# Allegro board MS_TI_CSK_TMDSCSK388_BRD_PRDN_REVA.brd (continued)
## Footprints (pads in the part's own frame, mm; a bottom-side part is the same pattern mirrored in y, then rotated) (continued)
XTAL4_FA-238V_130X105_SMD
  rect 1.397x1.194 smd: 1(-1.1,-0.8) 2(1.1,-0.8) 3(1.1,0.8) 4(-1.1,0.8)
XTAL_9HT10_130X60_SMD
  rect 0.991x1.803 smd: 1(-1.25,0) 2(1.25,0)

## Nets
DGND: C3.2 C4.2 C5.2 C6.2 C7.2 C8.2 C9.2 C12.2 C13.2 C14.2 C15.2 C16.2 C17.2 C18.2 C19.2 C20.2 C21.2 C22.2 C23.2 C24.2 C25.2 C26.2 C27.2 C28.2 C29.2 C30.2 C31.2 C32.2 C33.2 C34.2 C35.2 C36.2 C37.2 C38.2 C39.1 C40.2 C41.2 C42.2 C43.2 C44.2 C45.2 C46.1 C47.1 C48.1 C49.1 C50.1 C51.2 C52.2 C53.2 C54.2 C55.2 C56.2 C57.2 C58.2 C67.2 C68.2 C69.2 C70.2 C72.2 C73.2 C74.2 C76.2 C78.2 C79.2 C80.2 C81.2 C82.2 C83.2 C85.2 C86.1 C87.2 C88.2 C89.2 C90.2 C91.2 C92.2 C93.2 C94.2 C95.1 C96.1 C97.1 C99.1 C100.2 C101.2 C102.2 C103.2 C104.2 C105.2 C106.2 C107.2 C108.1 C109.1 C110.1 C111.1 C112.1 C113.2 C114.2 C115.2 C116.2 C117.2 C118.2 C119.2 C120.2 C121.1 C122.2 C123.2 C124.2 C125.2 C126.2 C127.2 C128.1 C129.2 C130.2 C131.2 C132.1 C133.1 C134.1 C135.2 C136.1 C137.2 C138.2 C139.1 C140.2 C141.2 C142.2 C143.2 C144.2 C145.2 C146.2 C147.2 C148.2 C149.1 C150.1 C151.2 C152.2 C153.2 C154.1 C155.2 C156.2 C157.2 C158.2 C159.2 C160.1 C161.1 C162.2 C163.2 C164.2 C165.2 C166.2 C167.1 C168.2 C169.1 C170.2 C171.2 C172.2 C173.2 C174.1 C175.1 C176.2 C177.2 C178.2 C179.1 C180.2 C181.2 C182.2 C183.2 C184.2 C185.2 C186.2 C187.2 C188.2 C189.2 D1.5(ANODE) J1.2(GND1) J1.3(GND2) J2.2(GND1) J2.3(GND2) J3.6 J3.11(GND1) J3.12(GND2) J3.18 J3.24 J3.33(GND3) J3.34(GND4) J3.55(GND5) J3.56(GND6) J3.67 J3.77(GND7) J3.78(GND8) J4.11(GND1) J4.12(GND2) J4.23 J4.28 J4.33(GND3) J4.34(GND4) J4.42 J4.45 J4.48 J4.55(GND5) J4.56(GND6) J4.62 J4.65 J4.77(GND7) J4.78(GND8) J5.5 J5.11(GND1) J5.12(GND2) J5.17 J5.33(GND3) J5.34(GND4) J5.35 J5.55(GND5) J5.56(GND6) J5.63 J5.64 J5.65 J5.66 L1.2 L2.2 L3.2 LD1.1(CATHODE) MOD1.1(GND#1) MOD1.7(GND#7) MOD1.9(GND#9) MOD1.15(GND#15) MOD1.16(GND#16) MOD1.17(GND#17) MOD1.19(GND#19) MOD1.20(GND#20) MOD1.23(GND#23) MOD1.24(GND#24) MOD1.28(GND#28) MOD1.29(GND#29) MOD1.30(GND#30) MOD1.31(GND#31) MOD1.33(GND#33) MOD1.34(GND#34) MOD1.35(GND#35) MOD1.37(GND#37) MOD1.39(GND#39) MOD1.44(GND#44) MOD1.45(GND#45) MOD1.48(GND#48) MOD1.49(GND#49) MOD1.54(GND#54) MOD1.55(GND#55) MOD1.59(GND#59) MOD1.61(GND#61) MOD1.63(GND#63) MOD1.64(RESERVED4) MOD1.G1(GND#G1) MOD1.G2(GND#G2) MOD1.G3(GND#G3) MOD1.G4(GND#G4) MOD1.G5(GND#G5) MOD1.G6(GND#G6) MOD1.G7(GND#G7) MOD1.G8(GND#G8) MOD1.G9(GND#G9) MOD1.G10(GND#G10) MOD1.G11(GND#G11) MOD1.G12(GND#G12) MOD1.G13(GND#G13) MOD1.G14(GND#G14) MOD1.G15(GND#G15) MOD1.G16(GND#G16) MOD1.G17(GND#G17) MOD1.G18(GND#G18) MOD1.G19(GND#G19) MOD1.G20(GND#G20) MOD1.G21(GND#G21) MOD1.G22(GND#G22) MOD1.G23(GND#G23) MOD1.G24(GND#G24) MOD1.G25(GND#G25) MOD1.G26(GND#G26) MOD1.G27(GND#G27) MOD1.G28(GND#G28) MOD1.G29(GND#G29) MOD1.G30(GND#G30) MOD1.G31(GND#G31) MOD1.G32(GND#G32) MOD1.G33(GND#G33) MOD1.G34(GND#G34) MOD1.G35(GND#G35) MOD1.G36(GND#G36) Q1.4(S1) Q1.7(S2) Q3.4(S1) Q3.7(S2) R1.1 R6.1 R11.2 R12.2 R16.2 R18.2 R28.2 R30.2 R31.2 R32.2 R33.2 R34.2 R46.2 R48.2 R49.2 R50.2 R51.2 R53.2 R56.2 R58.2 R61.2 R63.2 R64.1 R66.1 R76.1 R81.2 R83.2 R92.2 R97.1 R99.2 R101.2 R102.1 R112.1 R113.1 R119.1 R120.2 R122.2 R132.1 U1.A1(DGND_C) U1.A7(GND_CTRL_B) U1.A8(GND_CTRL_A) U1.B1(DGND_B) U1.B2(DGND_A) U1.C1(GND1_C) U1.C2(GND1_B) U1.D3(GND1_A) U1.D6(AGND_A) U1.E5(AGND_C) U1.E6(AGND_B) U1.F5(AGND_D) U1.G4(AGND_E) U1.H5(AGND_K) U1.H6(AGND_F) U1.J1(GND2_B) U1.J2(GND2_A) U1.J3(AGND_G) U1.J4(AGND_H) U1.J6(AGND_I) U1.J7(GNDIO_B) U1.J8(GNDIO_A) U1.K3(AGND_J) U1.M8(AGND2_B) U1.N8(AGND2_A) U2.8(GND1) U2.9(GND2) U2.14(2\O\E\) U2.15(1\O\E\) U2.17(PAD) U3.11(GND) U3.21(PAD) U4.8(GND) U4.9(3A) U4.12(4A) U4.15(O\E\) U4.17(EP) U5.8(GND1) U5.9(GND2) U5.14(2\O\E\) U5.15(1\O\E\) U5.17(PAD) U6.A9(VSS1) U6.B1(VSSQ1) U6.B3(VSS2) U6.B9(VSSQ2) U6.D1(VSSQ3) U6.D8(VSSQ4) U6.E1(VSS3) U6.E2(VSSQ5) U6.E8(VSSQ6) U6.F9(VSSQ7) U6.G1(VSSQ8) U6.G8(VSS4) U6.G9(VSSQ9) U6.J2(VSS5) U6.J8(VSS6) U6.M1(VSS7) U6.M9(VSS8) U6.P1(VSS9) U6.P9(VSS10) U6.T1(VSS11) U6.T9(VSS12) U7.A1(VSS#A1) U7.A31(VSS#A31) U7.AA13(VSS#AA13) U7.AA14(VSS#AA14) U7.AA15(VSS#AA15) U7.AA16(VSS#AA16) U7.AA17(VSS#AA17) U7.AA18(VSS#AA18) U7.AA27(VSS#AA27) U7.AC7(VSSA_CSI2#AC7) U7.AC25(VSS#AC25) U7.AD3(VSS#AD3) U7.AD4(VSS#AD4) U7.AD5(VSS#AD5) U7.AD6(VSS#AD6) U7.AD7(VSS#AD7) U7.AD24(VSS#AD24) U7.AD25(VSS#AD25) U7.AE5(VSS#AE5) U7.AE6(VSS#AE6) U7.AE7(VSS#AE7) U7.AE8(VSS#AE8) U7.AE9(VSS#AE9) U7.AE12(VSS#AE12) U7.AE19(VSS#AE19) U7.AE20(VSS#AE20) U7.AE23(VSS#AE23) U7.AE24(VSS#AE24) U7.AE25(VSS#AE25) U7.AE26(VSS#AE26) U7.AE27(VSS#AE27) U7.AE28(VSS#AE28) U7.AF7(VSS#AF7) U7.AF12(VSS#AF12) U7.AF20(VSS#AF20) U7.AF24(VSS#AF24) U7.AF25(VSS#AF25) U7.AG7(VSS#AG7) U7.AG11(VSS#AG11) U7.AG19(VSS#AG19) U7.AG24(VSS#AG24) U7.AG25(VSS#AG25) U7.AH7(VSS#AH7) U7.AH12(VSS#AH12) U7.AH20(VSS#AH20) U7.AL1(VSS#AL1) U7.AL31(VSS#AL31) U7.C8(VSSA_VDAC) U7.D8(VSS#D8) U7.D20(VSSA_USB#D20) U7.D25(VSS#D25) U7.E7(VSS#E7) U7.E8(VSS#E8) U7.E21(VSS#E21) U7.E25(VSS#E25) U7.F7(VSS#F7) U7.F8(VSS#F8) U7.F20(VSS#F20) U7.F25(VSS#F25) U7.G4(VSS#G4) U7.G5(VSS#G5) U7.G6(VSS#G6) U7.G7(VSS#G7) U7.G8(VSS#G8) U7.G9(VSSA_HDMI#G9) U7.G20(VSS#G20) U7.G23(VSS#G23) U7.G24(VSS#G24) U7.G25(VSS#G25) U7.G26(VSS#G26) U7.G27(VSS#G27) U7.H7(VSS#H7) U7.H8(VSSA_HDMI#H8) U7.H26(VSS#H26) U7.J7(VSS#J7) U7.L16(VSS#L16) U7.M16(VSS#M16) U7.N13(VSS#N13) U7.N14(VSS#N14) U7.N16(VSS#N16) U7.N17(VSS#N17) U7.N19(VSSA_USB#N19) U7.N20(VSSA_USB#N20) U7.P11(VSS#P11) U7.P12(VSS#P12) U7.P14(VSS#P14) U7.P18(VSS#P18) U7.R11(VSS#R11) U7.R12(VSS#R12) U7.R14(VSS#R14) U7.R18(VSS#R18) U7.R20(VSS#R20) U7.R21(VSS#R21) U7.T11(VSS#T11) U7.T12(VSS#T12) U7.T14(VSS#T14) U7.T15(VSS#T15) U7.T16(VSS#T16) U7.T19(VSS#T19) U7.T20(VSS#T20) U7.T21(VSS#T21) U7.U14(VSS#U14) U7.U18(VSS#U18) U7.U23(VSS#U23) U7.V14(VSSA_CSI2#V14) U7.V18(VSS#V18) U7.W16(VSS#W16) U7.W17(VSS#W17) U7.Y16(VSS#Y16) U7.Y17(VSS#Y17) U7.Y25(VSS#Y25) U7.Y26(VSS#Y26) U7.Y28(VSS#Y28) U8.A9(VSS1) U8.B1(VSSQ1) U8.B3(VSS2) U8.B9(VSSQ2) U8.D1(VSSQ3) U8.D8(VSSQ4) U8.E1(VSS3) U8.E2(VSSQ5) U8.E8(VSSQ6) U8.F9(VSSQ7) U8.G1(VSSQ8) U8.G8(VSS4) U8.G9(VSSQ9) U8.J2(VSS5) U8.J8(VSS6) U8.M1(VSS7) U8.M9(VSS8) U8.P1(VSS9) U8.P9(VSS10) U8.T1(VSS11) U8.T9(VSS12) U9.2(GND) U10.2(GND) U11.2(GND) U12.8(GND1) U12.9(GND2) U12.14(2\O\E\) U12.15(1\O\E\) U12.17(PAD) U13.13(VSS1) U13.25(VSS2) U13.36(VSS3) U13.48(VSS4) U14.4(VTTGND) U14.7(GND) U14.10(PGND) U14.21(EP)
VCC_3V3: C15.1 C20.1 C23.1 C35.1 C40.1 C45.1 C55.1 C56.1 C67.1 C69.1 C80.1 C81.1 C82.1 C83.1 C91.1 C100.1 C101.1 C102.1 C103.1 C114.1 C176.1 C177.1 C178.1 C181.1 C189.1 MOD1.46(VBAT_IN#46) MOD1.47(VBAT_IN#47) R7.1 R10.1 R20.1 R22.1 R23.1 R24.1 R25.1 R26.1 R29.1 R35.1 R40.1 R42.1 R43.1 R44.1 R45.1 R55.1 R57.1 R59.1 R60.1 R62.1 R67.1 R69.1 R70.1 R75.1 R84.1 R85.1 R91.1 R95.1 R96.1 R103.1 R118.2 R121.1 R130.1 R131.1 TP14.1(TP) U1.N7(VDDIO) U2.1(VCCA) U3.19(VCCB) U4.16(VCC) U5.1(VCCA) U7.D16(DVDD#D16) U7.E17(DVDD#E17) U7.F16(DVDD#F16) U7.L5(DVDD#L5) U7.M4(DVDD#M4) U7.M6(DVDD#M6) U7.M7(DVDD#M7) U7.N10(DVDD#N10) U7.N11(DVDD#N11) U7.R5(DVDD_GPMC#R5) U7.R7(DVDD_GPMC#R7) U7.T4(DVDD_GPMC#T4) U7.T6(DVDD_GPMC#T6) U7.T7(DVDD_GPMC#T7) U7.T25(DVDD_SD#T25) U7.T26(DVDD#T26) U7.T28(DVDD#T28) U7.U25(DVDD_SD#U25) U7.U27(DVDD#U27) U7.W5(DVDD_RGMII#W5) U7.W7(DVDD_RGMII#W7) U7.Y4(DVDD_RGMII#Y4) U7.Y6(DVDD_RGMII#Y6) U7.Y7(DVDD_RGMII#Y7) U9.1(IN) U9.3(EN) U10.4(VCC) U11.5(VCC) U12.1(VCCA) U13.12(VCC1) U13.34(VCC2) U13.37(VCC3) U13.39(VCC4)
VCC_5V0: C6.1 C7.1 C13.1 C14.1 C16.1 C17.1 C19.1 C22.1 C33.1 C38.1 C42.1 C78.1 J4.83 J4.85 J4.87 Q2.1(D1) Q2.2(D2) Q2.5(D3) Q2.6(D4) Q2.8(D5) Q4.1(D1) Q4.2(D2) Q4.5(D3) Q4.6(D4) Q4.8(D5) R88.1 R94.1 TP4.1(TP) U1.A5(V5IN) U1.B6(VCC7) U1.D8(VCC5) U1.E8(VCCS) U1.L1(VCC4) U1.N3(VCC3) U14.12(V5IN)
VCC_CAM: C118.1 J4.22 R117.1 R118.1 U7.D12(DVDD_C#D12) U7.E13(DVDD_C#E13) U7.F12(DVDD_C#F12) U7.G12(DVDD_C#G12) U7.G13(DVDD_C#G13)
VDD_DDR: C43.1 C51.1 C52.1 C53.1 C93.1 C98.1 C104.1 C105.1 C107.1 C121.2 C122.1 C127.1 C128.2 C135.1 C141.1 C143.1 C144.1 C145.1 C146.1 C147.1 C162.1 C163.1 C165.1 C166.1 C170.1 C173.1 C182.1 C183.1 C184.1 C185.1 C187.1 C188.1 L8.2 R72.1 U6.A1(VDDQ1) U6.A8(VDDQ2) U6.B2(VDD1) U6.C1(VDDQ3) U6.C9(VDDQ4) U6.D2(VDDQ5) U6.D9(VDD2) U6.E9(VDDQ6) U6.F1(VDDQ7) U6.G7(VDD3) U6.H2(VDDQ8) U6.H9(VDDQ9) U6.K2(VDD4) U6.K8(VDD5) U6.N1(VDD6) U6.N9(VDD7) U6.R1(VDD8) U6.R9(VDD9) U7.AB14(DVDD_DDR[0]#AB14) U7.AB15(DVDD_DDR[0]#AB15) U7.AB17(DVDD_DDR[0]#AB17) U7.AB18(DVDD_DDR[0]#AB18) U7.AC15(DVDD_DDR[0]#AC15) U7.AC17(DVDD_DDR[0]#AC17) U7.AC18(DVDD_DDR[0]#AC18) U7.AE15(DVDD_DDR[0]#AE15) U7.AE16(DVDD_DDR[0]#AE16) U7.AF16(DVDD_DDR[0]#AF16) U7.AG15(DVDD_DDR[0]#AG15) U7.AH16(DVDD_DDR[0]#AH16) U8.A1(VDDQ1) U8.A8(VDDQ2) U8.B2(VDD1) U8.C1(VDDQ3) U8.C9(VDDQ4) U8.D2(VDDQ5) U8.D9(VDD2) U8.E9(VDDQ6) U8.F1(VDDQ7) U8.G7(VDD3) U8.H2(VDDQ8) U8.H9(VDDQ9) U8.K2(VDD4) U8.K8(VDD5) U8.N1(VDD6) U8.N9(VDD7) U8.R1(VDD8) U8.R9(VDD9) U14.2(VLDOIN) U14.9(VDDQSNS)
VDD_DDR_VREF: C90.1 C106.1 C132.2 C142.1 C164.1 C186.1 U6.H1(VREFDQ) U6.M8(VREFCA) U7.AL18(VREFSSTL_DDR[0]) U8.H1(VREFDQ) U8.M8(VREFCA) U14.5(VTTREF)
VDDR_VTT: C47.2 C48.2 C49.2 C50.2 C92.1 C94.1 C95.2 C96.2 C97.2 C108.2 C109.2 C112.2 C154.2 C169.2 RA4.1 RA4.2 RA4.3 RA4.4 RA6.1 RA6.2 RA6.3 RA6.4 RA7.1 RA7.2 RA7.3 RA7.4 RA8.1 RA8.2 RA8.3 RA8.4 RA10.1 RA10.2 RA10.3 RA10.4 RA11.1 RA11.2 RA11.3 RA11.4 U14.1(VTTSNS) U14.3(VTT)
BB_PMIC_3V3: J4.76 J4.80 J4.82 J4.84 J4.86 J4.88 R27.2
BB_VCC3V3: J4.16 J4.18 J4.20 R75.2
CC_RST: J3.54 R84.2 U11.3(B)
CLK32OUT_PMIC: R19.2 R36.1
CLKIN32: R82.2 U7.AJ31(CLKIN32/CLKOUT0/TIM3_IO/GP3[31])
CORE_CVDD: C87.1 C88.1 C89.1 C124.1 C125.1 C126.1 C129.1 C131.1 C137.1 C138.1 C140.1 C153.1 R15.2 R141.2 U7.P15(CVDD#P15) U7.P17(CVDD#P17) U7.R15(CVDD#R15) U7.R17(CVDD#R17) U7.T13(CVDD#T13) U7.T17(CVDD#T17) U7.T18(CVDD#T18) U7.U11(CVDD#U11) U7.U12(CVDD#U12) U7.U15(CVDD#U15) U7.U17(CVDD#U17) U7.V11(CVDD#V11) U7.V12(CVDD#V12) U7.V15(CVDD#V15) U7.V17(CVDD#V17) U7.W13(CVDD#W13) U7.W14(CVDD#W14) U7.W19(CVDD#W19) U7.W20(CVDD#W20) U7.Y13(CVDD#Y13) U7.Y14(CVDD#Y14) U7.Y19(CVDD#Y19) U7.Y20(CVDD#Y20)
CVDD_ARM: C113.1 C120.1 C150.2 C151.1 R17.2 U7.K17(CVDD_ARM#K17) U7.L17(CVDD_ARM#L17) U7.L18(CVDD_ARM#L18) U7.M13(CVDD_ARM#M13) U7.M14(CVDD_ARM#M14) U7.M17(CVDD_ARM#M17)
CVDD_HDVICP: C39.2 C41.1 C158.1 C168.1 R21.2 U7.U20(CVDD_HDVICP#U20) U7.U21(CVDD_HDVICP#U21) U7.V20(CVDD_HDVICP#V20) U7.V21(CVDD_HDVICP#V21) U7.W22(CVDD_HDVICP#W22)
DDR_PGOOD: R103.2 U11.6(C) U14.20(PGOOD)
DM388_BT_EN: U7.M1(GPMC_A[16]/GP2[5]) U12.4(1A1)
DM388_BTMODE[0]: R55.2 R56.1 U7.W6(GPMC_D[0]/BTMODE[0]) U13.29(I/O0)
DM388_BTMODE[1]: R40.2 R46.1 U7.W4(GPMC_D[1]/BTMODE[1]) U13.30(I/O1)
DM388_BTMODE[2]: R28.1 SW1.2 U7.W3(GPMC_D[2]/BTMODE[2]) U13.31(I/O2)
DM388_BTMODE[3]: R43.2 R49.1 U7.U2(GPMC_D[3]/BTMODE[3]) U13.32(I/O3)
DM388_BTMODE[4]: R25.2 R33.1 U7.W9(GPMC_D[4]/BTMODE[4]) U13.41(I/O4)
DM388_BTMODE[5]: R16.1 U7.T5(GPMC_D[5]/BTMODE[5]) U13.42(I/O5)
DM388_BTMODE[6]: R18.1 U7.T3(GPMC_D[6]/BTMODE[6]) U13.43(I/O6)
DM388_BTMODE[7]: R23.2 R31.1 U7.T2(GPMC_D[7]/BTMODE[7]) U13.44(I/O7)
DM388_BTMODE[8]: R44.2 R50.1 U7.T1(GPMC_D[8]/BTMODE[8]) U13.26(I/O8)
DM388_BTMODE[9]: R42.2 R48.1 U7.T8(GPMC_D[9]/BTMODE[9]) U13.27(I/O9)
DM388_BTMODE[10]: R24.2 R32.1 U7.R6(GPMC_D[10]/BTMODE[10]) U13.28(I/O10)
DM388_BTMODE[11]: R60.2 R101.1 U7.R4(GPMC_D[11]/BTMODE[11]) U13.33(I/O11)
DM388_BTMODE[12]: R29.2 U7.R3(GPMC_D[12]/BTMODE[12]) U13.40(I/O12)
DM388_BTMODE[13]: R45.2 R51.1 U7.R2(GPMC_D[13]/BTMODE[13]) U13.45(I/O13)
DM388_BTMODE[14]: R26.2 R34.1 U7.R1(GPMC_D[14]/BTMODE[14]) U13.46(I/O14)
DM388_BTMODE[15]: R22.2 R30.1 U7.P2(GPMC_D[15]/BTMODE[15]) U13.47(I/O15)
DM388_CAM_DAT0: J3.1 U7.C2(VOUT[1]_R_CR[0]/CAM_D[0]/GPMC_A)
DM388_CAM_DAT1: J3.3 U7.C1(VOUT[1]_R_CR[1]/CAM_D[1]/GPMC_A)
DM388_CAM_DAT2: J3.5 U7.B2(VOUT[1]_G_Y_YC[0]/CAM_D[2]/GPMC)
DM388_CAM_DAT3: J3.7 U7.A2(VOUT[1]_G_Y_YC[1]/CAM_D[3]/GPMC)
DM388_CAM_DAT4: J3.9 U7.A3(VIN[0]B_FLD/CAM_D[4]/GP0[21])
DM388_CAM_DAT5: J3.13 U7.B4(VIN[0]A_FLD/CAM_D[5]/GP0[20])
DM388_CAM_DAT6: J3.15 U7.C5(VIN[0]B_DE/CAM_D[6]/GP0[19])
DM388_CAM_DAT7: J3.17 U7.B5(VIN[0]A_DE/CAM_D[7]/GP0[18])
DM388_CAM_DAT8: J3.19 U7.K11(VIN[0]A_D[16]/CAM_D[8]/I2C[2]_S)
DM388_CAM_DAT9: J3.21 U7.E12(VIN[0]A_D[17]/CAM_D[9]/EMAC[1]_)
DM388_CAM_DAT10: J3.23 U7.K10(VIN[0]A_D[18]/CAM_D[10]/EMAC[1])
DM388_CAM_DAT11: J3.25 U7.D7(VIN[0]A_D[19]/CAM_D[11]/EMAC[1])
DM388_CAM_DAT12: J3.27 U7.F9(VIN[0]A_D[20]/CAM_D[12]/EMAC[1])
DM388_CAM_DAT13: J3.29 U7.C7(VIN[0]A_D[21]/CAM_D[13]/EMAC[1])
DM388_CAM_DAT14: J3.31 U7.A6(VIN[0]A_D[22]/CAM_D[14]/EMAC[1])
DM388_CAM_DAT15: J3.35 U7.A5(VIN[0]A_D[23]/CAM_D[15]/EMAC[1])
DM388_CAM_FLD: J3.41 U4.2(1B1)
DM388_CAM_FLD_UT_CTSN: U4.4(1A) U7.J10(VOUT[1]_FLD/CAM_FLD/CAM_WEN/GPM)
DM388_CAM_HS: J3.37 U7.D5(VOUT[1]_B_CB_C[1]/CAM_HS/GPMC_A)
DM388_CAM_PCLK: J3.43 R142.2 U4.5(2B1)
DM388_CAM_PCLK_UT_RTSN: R142.1 U4.7(2A) U7.B3(VOUT[0]_FLD/CAM_PCLK/GPMC_A[12])
DM388_CAM_RESET: J3.47 U7.H16(VIN[0]A_D[13]_BD[5]/CAM_RESET/G)
DM388_CAM_SHUTTER: J3.51 U7.H13(VIN[0]A_D[15]_BD[7]/CAM_SHUTTER)
DM388_CAM_STROBE: J3.49 U7.F13(VIN[0]A_D[14]_BD[6]/CAM_STROBE/)
DM388_CAM_VS: J3.39 U7.H9(VOUT[1]_B_CB_C[0]/CAM_VS/GPMC_A)
DM388_CAM_WEN: J3.45 U7.H17(VIN[0]A_D[11]_BD[3]/CAM_WEN/GP2)
DM388_CSI_DX0: J4.38 U7.AB2(CSI2_DX[0])
DM388_CSI_DX1: J4.44 U7.AA1(CSI2_DX[1])
DM388_CSI_DX2: J4.50 U7.AA2(CSI2_DX[2])
DM388_CSI_DX3: J4.58 U7.W2(CSI2_DX[3])
DM388_CSI_DX4: J4.64 U7.V1(CSI2_DX[4])
DM388_CSI_DY0: J4.40 U7.AC2(CSI2_DY[0])
DM388_CSI_DY1: J4.46 U7.AB1(CSI2_DY[1])
DM388_CSI_DY2: J4.52 U7.Y2(CSI2_DY[2])
DM388_CSI_DY3: J4.60 U7.W1(CSI2_DY[3])
DM388_CSI_DY4: J4.66 U7.V2(CSI2_DY[4])
DM388_DDR0_A0: RA7.8 U6.N3(A0) U7.AL24(DDR[0]_A[0]) U8.N3(A0)
DM388_DDR0_A1: RA4.7 U6.P7(A1) U7.AC22(DDR[0]_A[1]) U8.P7(A1)
DM388_DDR0_A2: RA7.7 U6.P3(A2) U7.AJ23(DDR[0]_A[2]) U8.P3(A2)
DM388_DDR0_A3: RA8.6 U6.N2(A3) U7.AJ27(DDR[0]_A[3]) U8.N2(A3)
DM388_DDR0_A4: RA11.5 U6.P8(A4) U7.AK28(DDR[0]_A[4]) U8.P8(A4)
DM388_DDR0_A5: RA8.7 U6.P2(A5) U7.AH27(DDR[0]_A[5]) U8.P2(A5)
DM388_DDR0_A6: RA11.8 U6.R8(A6) U7.AK30(DDR[0]_A[6]) U8.R8(A6)
DM388_DDR0_A7: RA8.8 U6.R2(A7) U7.AG23(DDR[0]_A[7]) U8.R2(A7)
DM388_DDR0_A8: RA4.5 U6.T8(A8) U7.AL29(DDR[0]_A[8]) U8.T8(A8)
DM388_DDR0_A9: RA7.6 U6.R3(A9) U7.AK29(DDR[0]_A[9]) U8.R3(A9)
DM388_DDR0_A10: RA10.8 U6.L7(A10/AP) U7.AD23(DDR[0]_A[10]) U8.L7(A10/AP)
DM388_DDR0_A11: RA4.6 U6.R7(A11) U7.AK24(DDR[0]_A[11]) U8.R7(A11)
DM388_DDR0_A12: RA4.8 U6.N7(A12/B\C\) U7.AH23(DDR[0]_A[12]) U8.N7(A12/B\C\)
DM388_DDR0_A13: RA7.5 U6.T3(A13) U7.AK23(DDR[0]_A[13]) U8.T3(A13)
DM388_DDR0_A14: RA11.6 U6.T7(A14) U7.AL23(DDR[0]_A[14]) U8.T7(A14)
DM388_DDR0_BA0: RA8.5 U6.M2(BA0) U7.AK26(DDR[0]_BA[0]) U8.M2(BA0)
DM388_DDR0_BA1: RA11.7 U6.N8(BA1) U7.AF23(DDR[0]_BA[1]) U8.N8(BA1)
DM388_DDR0_BA2: RA10.5 U6.M3(BA2) U7.AH25(DDR[0]_BA[2]) U8.M3(BA2)
DM388_DDR0_CASN: RA6.7 U6.K3(C\A\S\) U7.AK25(DDR[0]_CASN) U8.K3(C\A\S\)
DM388_DDR0_CKE: RA10.7 U6.K9(CKE) U7.AD20(DDR[0]_CKE) U8.K9(CKE)
DM388_DDR0_CLK: R107.1 U6.J7(CK) U7.AL27(DDR[0]_CLK) U8.J7(CK)
DM388_DDR0_CLKN: R108.1 U6.K7(C\K\) U7.AK27(DDR[0]_CLKN) U8.K7(C\K\)
DM388_DDR0_CS0N: RA6.8 U6.L2(C\S\) U7.AB21(DDR[0]_CS[0]N) U8.L2(C\S\)
DM388_DDR0_DQ0: U6.E3(DQ0) U7.AL9(DDR[0]_D[0])
DM388_DDR0_DQ1: U6.F7(DQ1) U7.AK9(DDR[0]_D[1])
DM388_DDR0_DQ2: U6.F2(DQ2) U7.AK10(DDR[0]_D[2])
DM388_DDR0_DQ3: U6.F8(DQ3) U7.AJ11(DDR[0]_D[3])
DM388_DDR0_DQ4: U6.H3(DQ4) U7.AH11(DDR[0]_D[4])
DM388_DDR0_DQ5: U6.H8(DQ5) U7.AD9(DDR[0]_D[5])
DM388_DDR0_DQ6: U6.G2(DQ6) U7.AF11(DDR[0]_D[6])
DM388_DDR0_DQ7: U6.H7(DQ7) U7.AL12(DDR[0]_D[7])
DM388_DDR0_DQ8: U6.D7(DQ8) U7.AJ12(DDR[0]_D[8])
DM388_DDR0_DQ9: U6.C3(DQ9) U7.AG12(DDR[0]_D[9])
DM388_DDR0_DQ10: U6.C8(DQ10) U7.AD12(DDR[0]_D[10])
DM388_DDR0_DQ11: U6.C2(DQ11) U7.AB12(DDR[0]_D[11])
DM388_DDR0_DQ12: U6.A7(DQ12) U7.AK13(DDR[0]_D[12])
DM388_DDR0_DQ13: U6.A2(DQ13) U7.AC13(DDR[0]_D[13])
DM388_DDR0_DQ14: U6.B8(DQ14) U7.AL14(DDR[0]_D[14])
DM388_DDR0_DQ15: U6.A3(DQ15) U7.AK14(DDR[0]_D[15])
DM388_DDR0_DQ16: U7.AH15(DDR[0]_D[16]) U8.E3(DQ0)
DM388_DDR0_DQ17: U7.AF15(DDR[0]_D[17]) U8.F7(DQ1)
DM388_DDR0_DQ18: U7.AD15(DDR[0]_D[18]) U8.F2(DQ2)
DM388_DDR0_DQ19: U7.AK16(DDR[0]_D[19]) U8.F8(DQ3)
DM388_DDR0_DQ20: U7.AJ16(DDR[0]_D[20]) U8.H3(DQ4)
DM388_DDR0_DQ21: U7.AG16(DDR[0]_D[21]) U8.H8(DQ5)
DM388_DDR0_DQ22: U7.AD16(DDR[0]_D[22]) U8.G2(DQ6)
DM388_DDR0_DQ23: U7.AC16(DDR[0]_D[23]) U8.H7(DQ7)
DM388_DDR0_DQ24: U7.AK19(DDR[0]_D[24]) U8.D7(DQ8)
DM388_DDR0_DQ25: U7.AJ19(DDR[0]_D[25]) U8.C3(DQ9)
DM388_DDR0_DQ26: U7.AH19(DDR[0]_D[26]) U8.C8(DQ10)
DM388_DDR0_DQ27: U7.AF19(DDR[0]_D[27]) U8.C2(DQ11)
DM388_DDR0_DQ28: U7.AD19(DDR[0]_D[28]) U8.A7(DQ12)
DM388_DDR0_DQ29: U7.AC19(DDR[0]_D[29]) U8.A2(DQ13)
DM388_DDR0_DQ30: U7.AJ20(DDR[0]_D[30]) U8.B8(DQ14)
DM388_DDR0_DQ31: U7.AG20(DDR[0]_D[31]) U8.A3(DQ15)
DM388_DDR0_DQM0: U6.E7(LDM) U7.AL8(DDR[0]_DQM[0])
DM388_DDR0_DQM1: U6.D3(UDM) U7.AK12(DDR[0]_DQM[1])
DM388_DDR0_DQM2: U7.AJ15(DDR[0]_DQM[2]) U8.E7(LDM)
DM388_DDR0_DQM3: U7.AK18(DDR[0]_DQM[3]) U8.D3(UDM)
DM388_DDR0_DQS0: U6.F3(LDQS) U7.AL11(DDR[0]_DQS[0])
DM388_DDR0_DQS0N: U6.G3(L\D\Q\S\) U7.AK11(DDR[0]_DQS[0]N)
DM388_DDR0_DQS1: U6.C7(UDQS) U7.AL15(DDR[0]_DQS[1])
DM388_DDR0_DQS1N: U6.B7(U\D\Q\S\) U7.AK15(DDR[0]_DQS[1]N)
DM388_DDR0_DQS2: U7.AL17(DDR[0]_DQS[2]) U8.F3(LDQS)
DM388_DDR0_DQS2N: U7.AK17(DDR[0]_DQS[2]N) U8.G3(L\D\Q\S\)
DM388_DDR0_DQS3: U7.AL20(DDR[0]_DQS[3]) U8.C7(UDQS)
DM388_DDR0_DQS3N: U7.AK20(DDR[0]_DQS[3]N) U8.B7(U\D\Q\S\)
DM388_DDR0_ODT0: RA6.5 U6.K1(ODT) U7.AL21(DDR[0]_ODT[0]) U8.K1(ODT)
DM388_DDR0_RASN: RA6.6 U6.J3(R\A\S\) U7.AJ25(DDR[0]_RASN) U8.J3(R\A\S\)
DM388_DDR0_RST: R72.2 U6.T2(R\E\S\E\T\) U7.AA20(DDR[0]_RST) U8.T2(R\E\S\E\T\)
DM388_DDR0_VTP: R122.1 U7.AL30(DDR[0]_VTP)
DM388_DDR0_WEN: RA10.6 U6.L3(W\E\) U7.AL26(DDR[0]_WEN) U8.L3(W\E\)
DM388_EMU0: J3.30 R78.2
DM388_EMU1: J3.32 R77.2
DM388_GMII_COL: J4.54 U7.AH1(EMAC[0]_MCOL/EMAC[0]_RGRXCTL/VI)
DM388_GMII_CRS: J4.14 U7.AH2(EMAC[0]_MCRS/EMAC[0]_RGRXD[2]/V)
DM388_GMII_GMTCLK: J4.25 R73.1
DM388_GMII_MTCLK: J4.19 U7.AG4(EMAC[0]_MTCLK/EMAC[0]_RGRXC/VIN)
DM388_GMII_RCLK: J4.39 R106.2
DM388_GMII_RXD[0]: J4.47 R109.2
DM388_GMII_RXD[1]: J4.49 U7.AL2(EMAC[0]_MRXD[1]/EMAC[0]_RGRXD[0)
DM388_GMII_RXD[2]: J4.51 U7.AL3(EMAC[0]_MRXD[2]/EMAC[0]_RGRXD[1)
DM388_GMII_RXD[3]: J4.53 U7.AK3(EMAC[0]_MRXD[3]/EMAC[1]_RGRXCTL)
DM388_GMII_RXD[4]: J4.57 U7.AK4(EMAC[0]_MRXD[4]/EMAC[0]_RGRXD[3)
DM388_GMII_RXD[5]: J4.59 R104.2
DM388_GMII_RXD[6]: J4.61 R111.2
DM388_GMII_RXD[7]: J4.63 R110.2
DM388_GMII_RXDV: J4.41 U7.AJ6(EMAC[0]_MRXDV/EMAC[1]_RGRXD[1]/)
DM388_GMII_RXER: J4.43 U7.AJ2(EMAC[0]_MRXER/EMAC[0]_RGTXCTL/V)
DM388_GMII_TXD[0]: J4.17 RA2.5
DM388_GMII_TXD[1]: J4.15 RA2.6
DM388_GMII_TXD[2]: J4.13 RA2.7
DM388_GMII_TXD[3]: J4.9 RA2.8
DM388_GMII_TXD[4]: J4.7 RA3.5
DM388_GMII_TXD[5]: J4.5 RA3.6
DM388_GMII_TXD[6]: J4.3 RA3.7
DM388_GMII_TXD[7]: J4.1 RA3.8
DM388_GMII_TXEN: J4.27 R114.1
DM388_GP0[9]: J3.52 U7.AG30(AUD_CLKIN2/ATL_CLKOUT3/EDMA_EVT)
DM388_GP1[10]: J4.75 U7.AG1(EMAC_RMREFCLK/TIM2_IO/GP1[10])
DM388_GP1[14]: J4.74 U7.M5(GPMC_A[19]/TIM3_IO/GP1[14])
DM388_GP1[24]: J4.69 U7.AA12(GPMC_CS[1]N/GPMC_A[25]/GP1[24])
DM388_GP1[25]: J4.71 U7.AC3(GPMC_CS[2]N/GPMC_A[24]/GP1[25])
DM388_GP1[30]: J4.67 U7.Y11(GPMC_BE[1]N/GPMC_A[24]/EDMA_EVT)
DM388_GP3[3]: J4.73 U7.G2(VOUT[1]_B_CB_C[6]/EMAC[1]_MRXD[)
DM388_GP3[4]: J4.21 U7.H3(VOUT[1]_B_CB_C[7]/EMAC[1]_MRXD[)
DM388_GPMC_ALE: U7.AA10(GPMC_ADVN_ALE/GPMC_CS[6]N/TIM5_) U13.17(ALE)
DM388_GPMC_CLE: U7.Y3(GPMC_BE[0]N_CLE/GPMC_A[25]/EDMA) U13.16(CLE)
DM388_GPMC_CS[0]N: U7.AC9(GPMC_CS[0]N/GP1[23]) U13.9(C\E\)
DM388_GPMC_OEN_REN: U7.Y8(GPMC_OEN_REN) U13.8(R\E\)
DM388_GPMC_WAIT0: R20.2 U7.W8(GPMC_WAIT[0]/GPMC_A[26]/EDMA_EV) U13.7(R/B\)
DM388_GPMC_WEN: U7.Y5(GPMC_WEN) U13.18(W\E\)
DM388_GPMC_WPN: R35.2 U7.AF2(GPMC_CS[3]N/VIN[1]B_CLK/SPI[2]_) U13.19(W\P\)
DM388_HDMI_CEC: J4.6 U7.N2(GPMC_A[22]/SPI[2]_D[1]/HDMI_CEC)
DM388_HDMI_CLKN: J3.2 U7.B15(HDMI_CLKN)
DM388_HDMI_CLKP: J3.4 U7.A15(HDMI_CLKP)
DM388_HDMI_DN0: J3.8 U7.A14(HDMI_DN0)
DM388_HDMI_DN1: J3.14 U7.B13(HDMI_DN1)
DM388_HDMI_DN2: J3.20 U7.A12(HDMI_DN2)
DM388_HDMI_DP0: J3.10 U7.B14(HDMI_DP0)
DM388_HDMI_DP1: J3.16 U7.B12(HDMI_DP1)
DM388_HDMI_DP2: J3.22 U7.A11(HDMI_DP2)
DM388_HDMI_HPDET: J4.8 U7.R8(GPMC_A[23]/SPI[2]_SCLK/HDMI_HPD)
DM388_HDMI_SCL: J4.29 R67.2 U7.D2(I2C[1]_SCL/HDMI_SCL)
DM388_HDMI_SDA: J4.31 R70.2 U7.D1(I2C[1]_SDA/HDMI_SDA)
DM388_I2C0_SCL: R95.2 U1.M4(SCL) U7.T27(I2C[0]_SCL)
DM388_I2C0_SDA: R96.2 U1.M5(SDA) U7.T24(I2C[0]_SDA)
DM388_I2C2_SCL: J4.2 R130.2 U7.E31(UART0_DCDN/SPI[0]_SCS[3]N/I2C[2)
DM388_I2C2_SDA: J4.4 R121.2 U7.E29(UART0_DSRN/SPI[0]_SCS[2]N/I2C[2)
DM388_MCA[1]_AHCLKX: J3.79 R139.2
DM388_MCASP0_ACLKR: J5.23 R137.2
DM388_MCASP0_ACLKX: R52.1 R127.2
DM388_MCASP0_AFSR: J5.25 U7.AF30(MCA[0]_AFSR)
DM388_MCASP0_AFSX: R41.1 U7.AE29(MCA[0]_AFSX)
DM388_MCASP0_AXR0: R38.1 U7.AF29(MCA[0]_AXR[0])
DM388_MCASP0_AXR1: R90.1 U7.AE31(MCA[0]_AXR[1]/I2C[3]_SCL)
DM388_MCASP0_AXR2: J4.30 U7.AE30(MCA[0]_AXR[2]/I2C[3]_SDA)
DM388_MCASP0_AXR3: J4.32 U7.AC31(MCA[0]_AXR[3])
DM388_MCASP0_AXR4: J4.36 U7.AD26(MCA[0]_AXR[4])
DM388_MCASP0_AXR5: J4.79 U7.AD27(MCA[0]_AXR[5])
DM388_MCASP1_ACLKR: J5.21 R138.1
DM388_MCASP1_ACLKX: J3.81 R128.1
DM388_MCASP1_AFSR: J5.27 U7.AC24(MCA[1]_AFSR)
DM388_MCASP1_AFSX: J3.83 U7.AB22(MCA[1]_AFSX)
DM388_MCASP1_AXR0: J3.85 U7.Y22(MCA[1]_AXR[0]/SD0_DAT[4])
DM388_MCASP1_AXR1: J3.87 U7.Y21(MCA[1]_AXR[1]/SD0_DAT[5])
DM388_MDIO_CLK: J4.35 R65.1
DM388_MDIO_DAT: J4.37 U7.AG3(MDIO/GP1[12])
DM388_MMC0_CLK: R136.2 U3.20(B1)
DM388_MMC0_CMD: R126.2 U3.18(B2)
DM388_MMC0_DAT0: RA12.4 U3.17(B3)
DM388_MMC0_DAT1: RA12.3 U3.16(B4)
DM388_MMC0_DAT2: RA12.2 U3.15(B5)
DM388_MMC0_DAT3: RA12.1 U3.14(B6)
DM388_MMC1_CLK: J3.80 R135.1
DM388_MMC1_CMD: J3.82 R125.1
DM388_MMC1_DAT0: J3.84 RA13.5
DM388_MMC1_DAT1: J3.86 RA13.6
DM388_MMC1_DAT2: J3.88 RA13.7
DM388_MMC1_DAT3: J3.76 RA13.8
DM388_MMC1_DAT6/GP0_12: J4.70 U7.AB31(SD0_DAT[6]/GP0[12])
DM388_MMC1_DAT7/GP0_13: J4.72 U7.AC30(SD0_DAT[7]/GP0[13])
DM388_MMC1_SDCD: J3.75 U7.G28(SPI[0]_SCS[1]N/SD1_SDCD/EDMA_EV)
DM388_MMC2_CMD: J5.8 R105.2
DM388_MMC2_DAT0: J5.24 RA9.4
DM388_MMC2_DAT1: J5.22 RA9.3
DM388_MMC2_DAT2: J5.10 R115.2
DM388_MMC2_DAT3: J5.4 RA1.2
DM388_MMC2_DAT4: J5.6 RA1.1
DM388_MMC2_DAT5: J5.14 RA1.3
DM388_MMC2_DAT6: J5.16 RA1.4
DM388_MMC2_DAT7: J5.18 RA9.1
DM388_MMC2_DAT_0: RA9.5 U7.AC4(SD2_DAT[0]/GPMC_A[4]/GP1[14])
DM388_MMC2_DAT_1: RA9.6 U7.AC5(SD2_DAT[1]_SDIRQN/GPMC_A[3]/GP1)
DM388_MMC2_DAT_3: RA1.7 U7.AD1(SD2_DAT[3]/GPMC_A[1]/GP2[5])
DM388_MMC2_DAT_4: RA1.8 U7.AD2(SD2_DAT[4]/GPMC_A[27]/GPMC_A[23)
DM388_MMC2_DAT_5: RA1.6 U7.AE1(SD2_DAT[5]/GPMC_A[26]/GPMC_A[22)
DM388_MMC2_DAT_6: RA1.5 U7.AE2(SD2_DAT[6]/GPMC_A[25]/GPMC_A[21)
DM388_MMC2_DAT_7: RA9.8 U7.AE3(SD2_DAT[7]/GPMC_A[24]/GPMC_A[20)
DM388_MMC2_S_CLK: RA9.7 U7.AC6(SD2_SCLK/GP1[15])
DM388_MMC2_SCLK: J5.20 RA9.2
DM388_MUX_SEL: R53.1 U4.1(S) U7.N1(GPMC_A[21]/SPI[2]_D[0]/GP1[16])
DM388_PCIE_RXN0: J5.3 U7.J30(PCIE_RXN0)
DM388_PCIE_RXP0: J5.1 U7.K30(PCIE_RXP0)
DM388_PCIE_TXN0: C64.2 J5.9
DM388_PCIE_TXP0: C63.2 J5.7
DM388_PMIC_PWRON: J4.10 R94.2 U1.E4(PWRON)
DM388_PORN: R83.1 U7.AH30(PORN) U11.4(Y)
DM388_RSTOUT: J3.50 R81.1 U7.AJ30(RSTOUTN_WD_OUTN)
DM388_RTCK: J3.40 R124.2
DM388_SERDES_CLKN: C66.2 J5.15
DM388_SERDES_CLKP: C65.2 J5.13
DM388_SPI0_SCS[0]N: J3.70 U7.G29(SPI[0]_SCS[0]N)
DM388_SPI1_D[0]: J5.62 U7.N23(SPI[1]_D[0]/GP1[26])
DM388_SPI1_D[1]: J5.29 U7.M27(SPI[1]_D[1]/GP1[18])
DM388_SPI1_SCLK: J5.31 R123.2
DM388_SPI1_SCS[0]N: J5.61 U7.J29(SPI[1]_SCS[0]N/GP1[16])
DM388_SPI[0]_D[0]: J3.72 U7.J28(SPI[0]_D[0])
DM388_SPI[0]_D[1]: J3.74 U7.J27(SPI[0]_D[1])
DM388_SPI[0]_SCLK: J3.68 R129.2
DM388_TCLK: J3.38 U7.T29(TCLK)
DM388_TDI: J3.44 U7.N28(TDI)
DM388_TDO: J3.46 R133.2
DM388_TMS: J3.36 U7.T31(TMS)
DM388_TPS_SLEEP: U1.F1(SLEEP) U7.N9(GPMC_A[20]/SPI[2]_SCS[1]N/GP1[1)
DM388_TRSTN: J3.42 R120.1 U7.U24(TRSTN)
DM388_UART0_CTSN: J5.39 U7.D30(UART0_CTSN/SPI[1]_SCS[3]N/SD0_S)
DM388_UART0_RTSN: J5.37 U7.D31(UART0_RTSN/SPI[1]_SCS[2]N/SD2_S)
DM388_UART0_RXD: J3.71 U7.J26(UART0_RXD)
DM388_UART0_TXD: J3.69 R80.1
DM388_UART1_RXD: J3.28 U7.N26(UART0_RIN/UART1_RXD/GP1[5])
DM388_UART1_TXD: J3.26 R134.1
DM388_UART2_CTSN: U2.7(2A2) U4.3(1B2)
DM388_UART2_RTSN: U2.5(1A2) U4.6(2B2)
DM388_UART2_RXD: U2.6(2A1) U7.L22(UART2_RXD/I2C[3]_SCL/GP1[1])
DM388_UART2_TXD: R79.1 U2.4(1A1)
DM388_USB0_CE: J5.58 U7.B20(USB0_CE)
DM388_USB0_DM: J3.62 U7.B21(USB0_DM)
DM388_USB0_DP: J3.64 U7.A21(USB0_DP)
DM388_USB0_DRVVBUS: J3.66 U7.K23(USB0_DRVVBUS/GP0[7])
DM388_USB0_ID: J3.60 U7.A20(USB0_ID)
DM388_USB0_VBUSIN: J3.58 U7.B22(USB0_VBUSIN)
DM388_USB1_CE: J5.60 U7.C21(USB1_CE)
DM388_USB1_DM: J3.61 U7.B23(USB1_DM)
DM388_USB1_DP: J3.59 U7.A23(USB1_DP)
DM388_USB1_DRVVBUS: J3.63 U7.AF31(AUD_CLKIN0/MCA[0]_AHCLKX/ATL_CL)
DM388_USB1_ID: J3.65 U7.A24(USB1_ID)
DM388_USB1_VBUSIN: J3.57 U7.B24(USB1_VBUSIN)
DM388_VIN[0]A_CLK: J5.40 U7.C9(VIN[0]A_CLK/GP2[2])
DM388_VIN[0]A_D[0]: J5.46 U7.B18(VIN[0]A_D[0]/GP1[11])
DM388_VIN[0]A_D[1]: J5.49 U7.A17(VIN[0]A_D[1]/GP1[12])
DM388_VIN[0]A_D[2]: J5.50 U7.B17(VIN[0]A_D[2]/GP2[7])
DM388_VIN[0]A_D[3]: J5.52 U7.C17(VIN[0]A_D[3]/GP2[8])
DM388_VIN[0]A_D[4]: J5.54 U7.D17(VIN[0]A_D[4]/GP2[9])
DM388_VIN[0]A_D[5]: J5.53 U7.F17(VIN[0]A_D[5]/GP2[10])
DM388_VIN[0]A_D[6]: J5.59 U7.L20(VIN[0]A_D[6]/GP2[11])
DM388_VIN[0]A_D[7]: J5.57 U7.H20(VIN[0]A_D[7]/GP2[12])
DM388_VIN[0]A_D[8]_BD[0]: J5.47 U7.B16(VIN[0]A_D[8]_BD[0]/GP2[13])
DM388_VIN[0]A_D[9]_BD[1]: J5.48 U7.C16(VIN[0]A_D[9]_BD[1]/GP2[14])
DM388_VIN[0]A_D[10]_BD[2]: J5.45 U7.E16(VIN[0]A_D[10]_BD[2]/GP2[15])
DM388_VIN[0]A_D[12]_BD[4]: J5.51 U7.J16(VIN[0]A_D[12]_BD[4]/CLKOUT1/GP2)
DM388_VIN[0]A_DE: J5.42 U7.C12(VIN[0]A_DE/VIN[0]B_HSYNC/I2C[2])
DM388_VIN[0]A_FLD: J5.26 U7.J13(VIN[0]A_FLD/VIN[0]B_VSYNC/I2C[2)
DM388_VIN[0]A_HSYNC: J5.32 U7.D13(VIN[0]A_HSYNC/GP2[3])
DM388_VIN[0]A_VSYNC: J5.19 U7.C13(VIN[0]A_VSYNC/GP2[4])
DM388_VIN[0]B_CLK: J5.44 U7.H12(VIN[0]B_CLK/CLKOUT0/GP1[9])
DM388_WARM_RSTN: J3.48 R131.2 U7.AH29(RESETN)
DM388_WLAN_CLKOUT: R36.2 R37.2 U5.7(2A2)
DM388_WLAN_CLKOUT1: R37.1 R116.1
DM388_WLAN_EN: U7.M2(GPMC_A[17]/GP2[6]) U12.5(1A2)
DM388_WLAN_IRQ: U7.M3(GPMC_A[18]/TIM2_IO/GP1[13]) U12.7(2A2)
EN_LS_3V3: J4.68 R9.2 U1.L4(GPIO7)
EN_TPS51216: U1.L5(GPIO0) U14.16(S5) U14.17(S3)
ENET_RSTN: J4.81 U7.L2(VOUT[1]_G_Y_YC[2]/GPMC_A[13]/VI)
HDDAC_A: J5.28 R112.2 U7.A9(HDDAC_A)
HDDAC_B: J5.30 R113.2 U7.A8(HDDAC_B)
HDDAC_C: J5.41 R64.2 U7.B8(HDDAC_C)
HDDAC_HSYNC: J5.36 U7.E9(HDDAC_HSYNC)
HDDAC_VREF: C46.2 R66.2 R68.2 U7.B7(HDDAC_VREF)
HDDAC_VSYNC: J5.38 U7.D9(HDDAC_VSYNC)
NRESPWRON2: R7.2 U1.C7(NRESPWRON2) U11.1(A)
OSC_WAKE: J3.73 U7.U28(DEVOSC_WAKE/SPI[1]_SCS[1]N/TIM5)
PLL_1V8: C8.1 C119.1 C139.2 C149.2 C152.1 C160.2 C171.1 U1.C8(LDO4) U7.AA19(VDDA_DDRPLL_1P8) U7.L13(VDDA_VIDPLL_1P8) U7.L19(VDDA_ARMPLL_1P8) U7.T23(VDDA_HDVICPPLL_1P8) U7.V9(VDDA_AUDIOPLL_1P8) U7.W11(VDDA_L3L4_1P8)
PMIC_3V3: C9.1 C31.1 C32.1 C34.1 C37.1 C74.1 R27.1 TP13.1(TP) U1.E1(VCC1_C) U1.F2(VCC1_B) U1.F3(VCC1_A) U1.G1(VCC2_B) U1.G2(VCC2_A) U1.L7(VCCIO_B) U1.L8(VCCIO_A) U1.N5(VCC6)
REFGND: C10.1 C11.1 C71.1 R6.2 U1.G7(REFGND)
RF_ANT1: MOD1.32(RF_ANT1) R2.1 R4.1
RF_ANT2: MOD1.18(RF_ANT2) R3.1 R5.1
TPS_CORE_CVDD: C12.1 C190.1 L5.2 R15.1 TP3.1(TP)
TPS_CVDD_ARM: C25.1 C28.1 L6.2 R17.1 TP11.1(TP) U1.D4(VFB1)
TPS_CVDD_HDVICP: C27.1 C30.1 L7.2 R21.1 U1.K2(VFB2)
TPS_GPIO_3V3: C70.1 R9.1 U1.E7(LDO3)
TPS_HDMI_CSI_1V8: C21.1 C110.2 C123.1 U1.N4(LDO2) U7.K14(VDDA_HDMI_1P8) U7.W10(VDDA_CSI2_1P8)
TPS_INT1: J5.2 TP8.1(TP) U1.L3(INT1) U7.AH31(NMIN)
TPS_LDO5_3V3: C76.1 U1.K1(LDO5)
TPS_LDO6_3V3: C26.1 U1.M2(LDO6)
TPS_USB_1V8: C29.1 C136.2 C148.1 U1.M1(LDO8) U7.J17(VDDA_USB1_1P8) U7.K19(VDDA_USB0_1P8)
TPS_USB_3V3: C79.1 C167.2 C172.1 U1.M3(LDO7) U7.M19(VDDA_USB_3P3#M19) U7.M20(VDDA_USB_3P3#M20)
TPS_VDAC_1V8: C18.1 R8.1 TP7.1(TP) U1.N6(LDO1)
TPS_VDDA_1V8: C3.1 C4.1 C5.1 C24.1 C36.1 C44.1 C68.1 C115.1 C116.1 C117.1 C156.1 C157.1 C159.1 J4.24 L4.2 MOD1.38(VIO) R14.1 R86.1 R117.2 TP1.1(TP) U1.H8(VFBIO) U2.16(VCCB) U3.2(VCCA) U5.16(VCCB) U7.M25(VDDA_1P8#M25) U7.M26(VDDA_PCIE_1P8) U7.M28(RSV54) U7.N22(VDDA_1P8#N22) U7.N25(VDDA_1P8#N25) U7.N27(RSV55) U7.P20(VDDS_OSC1_1P8) U7.P21(VDDS_OSC0_1P8) U7.P23(VDDA_1P8#P23) U7.R9(VDDA_1P8#R9) U7.T9(VDDA_1P8#T9) U7.T10(VDDA_1P8#T10) U12.16(VCCB)
TPS_VHD_1V1: C58.1 C130.1 TP15.1(TP) U7.K16(VDDA_HDDAC_1P1) U9.5(OUT)
TV_OUT0: J3.53 R74.1 U7.B9(TV_OUT0)
VBACKUP: C72.1 J5.43 U1.D7(VBACKUP)
VDAC_1V8: C133.2 C134.2 R8.2 U7.J14(VDDA_VDAC_1P8) U7.L14(VDDA_HDDAC_1P8) U7.L15(VDDA_HDDACREF_1P8)
VREF_1.24V: C54.1 D1.4(REF) R68.1 R71.1
VRTC: C73.1 R98.1 U1.B5(VRTC)
WL_DM388_BT_EN: MOD1.41(BT_EN) U12.13(1B1)
WL_DM388_MCASP0_ACLKX: R13.1 R54.2
WL_DM388_MCASP0_AFSX: MOD1.58(BT_AUD_FSYNC) R47.2
WL_DM388_MCASP0_AXR0: MOD1.56(BT_AUD_IN) R39.2
WL_DM388_MCASP0_AXR1: MOD1.57(BT_AUD_OUT) R87.2
WL_DM388_MMC0_CLK: R89.1 U3.1(A1)
WL_DM388_MMC0_CMD: R93.1 U3.3(A2)
WL_DM388_MMC0_DAT0: RA5.5 U3.4(A3)
WL_DM388_MMC0_DAT1: RA5.6 U3.5(A4)
WL_DM388_MMC0_DAT2: RA5.7 U3.6(A5)
WL_DM388_MMC0_DAT3: RA5.8 U3.7(A6)
WL_DM388_UART2_CTSN: MOD1.50(BT_HCI_RTS) U2.10(2B2)
WL_DM388_UART2_RTSN: MOD1.51(BT_HCI_CTS) U2.12(1B2)
WL_DM388_UART2_RXD: MOD1.52(BT_HCI_TX) U2.11(2B1)
WL_DM388_UART2_TXD: MOD1.53(BT_HCI_RX) U2.13(1B1)
WL_DM388_WLAN_CLKOUT: MOD1.36(EXT_32K) U5.10(2B2)
WL_DM388_WLAN_EN: MOD1.40(WLAN_EN) U12.12(1B2)
WL_DM388_WLAN_IRQ: MOD1.14(WLAN_IRQ) R86.2 U12.10(2B2)
XTAL_GND1: C59.1 C62.1 U7.G30(VSSA_DEVOSC) Y2.2 Y2.4
XTAL_GND2: C60.1 C61.2 U7.U30(VSSA_AUXOSC) Y3.2 Y3.4
N11812612: C98.2 R107.2 R108.2
N11838777: C111.2 U7.AB10(LDOCAP_RAM2)
N11838793: C179.2 U7.Y24(LDOCAP_HDVICPRAM)
N11838802: C99.2 U7.U9(LDOCAP_RAM0)
N11838814: C175.2 U7.T22(LDOCAP_RAM1)
N11846918: C161.2 U7.K20(LDOCAP_ARMRAM)
N11847334: L6.1 U1.D1(SW1_C) U1.D2(SW1_B) U1.E2(SW1_A)
N11848351: L7.1 U1.H1(SW2_B) U1.H2(SW2_A)
N11848810: L4.1 U1.K7(SWIO_B) U1.K8(SWIO_A)
N11883885: RA2.4 U7.AK6(EMAC[0]_MTXD[0]/EMAC[1]_RGRXD[3)
N11883897: RA2.3 U7.AJ7(EMAC[0]_MTXD[1]/EMAC[1]_RGTXD[1)
N11883909: RA2.2 U7.AK7(EMAC[0]_MTXD[2]//EMAC[1]_RGTXCT)
N11883921: RA2.1 U7.AE4(EMAC[0]_MTXD[3]/EMAC[1]_RGTXD[0)
N11883933: RA3.4 U7.AK8(EMAC[0]_MTXD[4]/EMAC[1]_RGTXD[2)
N11883945: RA3.3 U7.AJ8(EMAC[0]_MTXD[5]/EMAC[1]_RGTXC/E)
N11883957: RA3.2 U7.AH8(EMAC[0]_MTXD[6]/EMAC[1]_RGRXD[0)
N11883969: RA3.1 U7.AG8(EMAC[0]_MTXD[7]/EMAC[1]_RGTXD[3)
N12895522: C62.2 U7.G31(DEVOSC_MXO) Y2.3
N12895682: C61.1 U7.V30(AUXOSC_MXI) Y3.3
N12895686: C60.2 U7.U31(AUXOSC_MXO) Y3.1
N12909578: C11.2 U1.F7(OSC32KOUT) Y1.1
N12909638: C10.2 U1.F8(OSC32KIN) Y1.2
N12910002: C71.2 U1.G8(VREF)
N12911225: R97.2 U1.N2(PWRDN)
N12911351: R98.2 U1.J5(BOOT1)
N12969077: C174.2 U7.M24(LDOCAP_SERDESCLK)
N12971691: R12.1 U1.B3(TRIP)
N12971710: C75.1 U1.C5(VFB)
N12972021: C75.2 C190.2 R141.1 U1.B4(VOUT)
N12972241: Q2.3(G) U1.A3(DRVH)
N12972253: Q1.3(G) U1.A6(DRVL)
N12973009: C77.1 U1.A2(VBST)
N12973023: C77.2 L5.1 Q1.1(D1) Q1.2(D2) Q1.5(D3) Q1.6(D4) Q1.8(D5) Q2.4(S1) Q2.7(S2) U1.A4(SW)
N12985066: R85.2 U10.1(EOH)
N12985136: R82.1 U10.3(OUTPUT)
N12993482: R132.2 U8.L8(ZQ)
N14066974: Q3.3(G) U14.11(DRVL)
N14067031: Q4.3(G) U14.14(DRVH)
N14067125: C84.2 L8.1 Q3.1(D1) Q3.2(D2) Q3.5(D3) Q3.6(D4) Q3.8(D5) Q4.4(S1) Q4.7(S2) U14.13(SW)
N14068093: R99.1 U14.18(TRIP)
N14068298: C85.1 R61.1 R100.2 U14.8(REFIN)
N14068467: C86.2 R100.1 U14.6(VREF)
N14068656: R102.2 U14.19(MODE)
N14068754: C84.1 U14.15(VBST)
N14086942: R14.2 U3.10(OE)
N14162633: C57.1 U9.4(NR/FB)
N14387261: R10.2 U2.2(1DIR)
N14387269: R11.1 U2.3(2DIR)
N14434808: C155.1 U7.J19(LDOCAP_ARM)
N14434812: C180.1 U7.W23(LDOCAP_HDVICP)
N14445231: TP9.1(TP) U1.N1(PWRHOLD)
N14486422: LD1.2(ANODE) R88.2
N14519770: R63.1 U7.B6(HDDAC_IREF)
N14522090: R73.2 U7.AL6(EMAC[0]_GMTCLK/EMAC[1]_RGRXC/GP)
N14522146: R114.2 U7.AF8(EMAC[0]_MTXEN/EMAC[1]_RGRXD[2]/)
N14553661: R116.2 U7.AB9(GPMC_CLK/GPMC_CS[5]N/GPMC_WAIT[)
N14554807: TP12.1(TP) U1.L2(GPIO2)
N14554839: TP10.1(TP) U1.G3(GPIO6)
N14559309: R104.1 U7.AJ4(EMAC[0]_MRXD[5]/EMAC[0]_RGTXD[3)
N14559352: R110.1 U7.AK5(EMAC[0]_MRXD[7]/EMAC[0]_RGTXD[1)
N14559366: R111.1 U7.AL5(EMAC[0]_MRXD[6]/EMAC[0]_RGTXD[2)
N14559434: R109.1 U7.AK2(EMAC[0]_MRXD[0]/EMAC[0]_RGTXD[0)
N14564270: R52.2 U5.4(1A1)
N14564274: R41.2 U5.5(1A2)
N14564278: R38.2 U5.6(2A1)
N14564302: R57.2 U5.3(2DIR)
N14564360: R58.1 R62.2 U5.2(1DIR)
N14565290: R92.1 U12.3(2DIR)
N14565662: R91.2 U12.2(1DIR)
N14567220: R136.1 U7.AB30(SD0_CLK/GP0[1])
N14567296: R135.2 U7.W30(SD1_CLK)
N14568444: R127.1 U7.AD28(MCA[0]_ACLKX)
N14568464: R128.2 U7.AC23(MCA[1]_ACLKX)
N14568476: R139.1 U7.AF27(AUD_CLKIN1/MCA[1]_AHCLKX/ATL_CL)
N14572177: MOD1.42(WL_UART_DBG) TP6.1(TP)
N14572181: MOD1.43(BT_UART_DBG) TP5.1(TP)
N14575481: A1.1(FEED_A1) C2.2 L3.1
N14575485: A2.1(FEED_A1) C1.2 L2.1
N14575533: C2.1 R1.2 R4.2
N14575591: C1.1 L1.1 R5.2
N14595953: D1.3(CATHODE) R69.2 R71.2
N14599932: R78.1 U7.B19(EMU1)
N14599936: R77.1 U7.A18(EMU0)
N14600104: R124.1 U7.N29(RTCK)
N14600252: C64.1 U7.K31(PCIE_TXN0)
N14600256: C63.1 U7.L31(PCIE_TXP0)
N14600268: C66.1 U7.H31(SERDES_CLKN)
N14600316: C65.1 U7.H30(SERDES_CLKP)
N14600424: R74.2 U7.B10(TV_VFB0)
N14600444: R76.2 U7.B11(TV_RSET)
N14634458: R59.2 SW1.1
N14645029: TP2.1(TP) U1.L6(HDRST)
N14648093: C59.2 U7.F30(DEVOSC_MXI/DEV_CLKIN) Y2.1
N14719275: R19.1 U1.F4(CLK32KOUT)
N14719324: R106.1 U7.AK1(EMAC[0]_MRCLK/EMAC[0]_RGTXC/VIN)
N14776629: R138.2 U7.AD29(MCA[1]_ACLKR)
N14776712: R137.1 U7.AD30(MCA[0]_ACLKR)
N14776785: R129.1 U7.N24(SPI[0]_SCLK)
N14776789: R123.1 U7.M29(SPI[1]_SCLK/GP1[17])
N14783196: RA13.4 U7.W31(SD1_DAT[0])
N14783200: RA13.3 U7.AA30(SD1_DAT[1]_SDIRQN)
N14783204: RA13.2 U7.U29(SD1_DAT[2]_SDRWN)
N14783208: RA13.1 U7.Y27(SD1_DAT[3])
N15013442: J1.1(FEED) R2.2
N15014410: J2.1(FEED) R3.2
N15102842: R79.2 U7.M21(UART2_TXD/I2C[3]_SDA/GP1[0])
N15102865: R134.2 U7.E30(UART0_DTRN/UART1_TXD/GP1[4])
N15102869: R80.2 U7.E28(UART0_TXD)
N15102988: R65.2 U7.AG2(MDCLK/GP1[11])
N15110091: R54.1 U5.13(1B1)
N15110100: R47.1 U5.12(1B2)
N15110106: R39.1 U5.11(2B1)
N15110404: R87.1 U12.11(2B1)
N15110444: R90.2 U12.6(2A1)
N15123588: R125.2 U7.Y29(SD1_CMD/GP0[0])
N15123674: R126.1 U7.AA29(SD0_CMD/SD1_CMD/GP0[2])
N15123798: RA12.5 U7.AA28(SD0_DAT[0]/SD1_DAT[4]/GP0[3])
N15123807: RA12.6 U7.AA26(SD0_DAT[1]_SDIRQN/SD1_DAT[5]/GP)
N15123817: RA12.7 U7.Y31(SD0_DAT[2]_SDRWN/SD1_DAT[6]/GP0)
N15123828: RA12.8 U7.Y30(SD0_DAT[3]/SD1_DAT[7]/GP0[6])
N15124532: R105.1 U7.AG6(GPMC_CS[4]N/SD2_CMD/GP1[8])
N15124704: MOD1.6(WL_SDIO_CMD) R93.2
N15124708: MOD1.8(WL_SDIO_CLK) R89.2
N15124784: MOD1.10(WL_SDIO_D0) RA5.4
N15124788: MOD1.11(WL_SDIO_D1) RA5.3
N15124799: MOD1.13(WL_SDIO_D3) RA5.1
N15124807: MOD1.12(WL_SDIO_D2) RA5.2
N15124875: MOD1.60(BT_AUD_CLK) R13.2
N15140205: R119.2 U6.L8(ZQ)
N15266407: R115.1 U7.AC8(SD2_DAT[2]_SDRWN/GPMC_A[2]/GP2[)
N15454827: R133.1 U7.U26(TDO)

Pads without a net: A1 2; A2 2; D1 1 2; J4 26; MOD1 2 3 4 5 21 22 25 26 27 62; U1 B7 B8 C4 C6 D5 F6 G6 H4 H7 K5 M6 M7; U3 8 9 12 13; U4 10 11 13 14; U6 J1 J9 L1 L9 M7; U7 A26 A27 A29 A30 AD8 AH24 AJ24 AK21 AK22 B25 B26 B27 B28 B29 B30 B31 C20 C24 C25 C26 C28 C30 D3 D21 D24 E2 E20 E24 E26 F1 F2 F3 F5 F21 F24 G1 G3 G16 G17 H2 H4 H5 H6 H23 H24 H25 H27 H28 H29 J1 J2 J8 J9 J23 J24 J25 K1 K2 K22 L3 L4 L6 L12 L30 M8 M10 M11 M30 N30 N31 P30 P31 R30 T30; U8 J1 J9 L1 L9 M7; U13 1 2 3 4 5 6 10 11 14 15 20 21 22 23 24 35 38

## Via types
v1: diameter 0.457, hole 0.254, TOP to BOTTOM, 1729 vias
v2: diameter 0.508, hole 0.254, TOP to BOTTOM, 19 vias

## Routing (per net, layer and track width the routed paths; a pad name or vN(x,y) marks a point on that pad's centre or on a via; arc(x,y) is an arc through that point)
DGND: length 669.8
  TOP w0.102: U1.A1 30.1,48.07 v1(30.42,47.75) ; U1.J3 U1.J2 U1.J1 ; U7.AE9 U7.AE8 ; U1.C2 U1.B2 ; v2(55.99,9.75) 55.99,9.71 55.61,9.34 U7.A31
  TOP w0.14: v1(49.76,57.28) 49.9,57.42 49.9,57.62 C5.2 ; C15.2 v1(49.14,52.39) ; MOD1.59 v1(60.45,48.34) ; C20.2 v1(49.14,51.37) ; MOD1.20 v1(62.55,62.78) ; MOD1.49 v1(52.21,49.87) ; MOD1.19 63.25,62.72 62.6,63.36 v1(62.6,63.87) ; MOD1.54 v1(56.95,49) ; MOD1.55 v1(57.65,48.34)
  TOP w0.152: U7.AF12 42.98,18.73 v1(43.33,18.37) 43.48,18.51 U7.AE12 U7.AF12 ; U7.AF12 U7.AG11 U7.AH12 41.98,18.56 v1(42.17,18.37) ; U7.E21 U7.F20 U7.G20 ; U7.E21 U7.D20 ; U7.E21 U7.G23 U7.G24 ; U7.E21 53.48,13.65 v1(53.6,13.54) ; v1(52.98,11.88) 52.98,11.9 ; v1(42.97,21.89) 42.98,21.89 ; U7.AE19 43.48,15.68 v1(43.41,15.75) ; U7.AH20 U7.AG19 U7.AF20 ; v1(46.47,10.97) 46.33,10.84 U7.Y28 U7.AA27 U7.Y26 U7.Y25 ; U7.U23 47.49,13.34 47.65,13.5 47.65,14.02 U7.T21 ; U7.E7 U7.E8 ; U1.F5 33.5,50.52 v1(33.81,50.52) 33.81,50.21 U1.G4 ; U1.J4 v1(35.62,49.7) ; v1(35.62,49.7) 35.95,49.38 U1.K3 ; v1(35.62,49.7) U1.J3 ; v1(47.43,15.37) 47.41,15.37 46.98,15.8 U7.V18 ; U7.V14 U7.U14 ; v1(49.43,18.87) 49.43,18.92 49.02,19.34 U7.P11
  TOP w0.178: C24.2 v1(52.3,48.89) ; C36.2 63.63,38.74 63.48,38.58 v1(63.48,38.05) ; C23.2 v1(50.82,48.89) ; C35.2 v1(60.8,38.81) ; C54.2 59.15,24.72 59.08,24.64 59.05,24.64 58.92,24.77 v1(58.45,24.77) ; U1.E6 32.92,51.1 v1(32.92,51) 32.92,50.9 32.7,50.68 U1.E5 ; U1.D6 32.29,51.08 v1(32.34,51.08) ; 14.85,21.41 14.79,21.35 C56.2 ; 15.78,39.95 C37.2
  TOP w0.203: 31.4,47.12 U1.C1 U1.C2 U1.D3 ; U1.A7 29.05,53.02 ; U1.J1 35.3,46.76 ; U1.J7 U1.J8 35.3,53.8 v1(35.46,53.97) ; v1(69.22,30.28) 69.85,30.91 69.85,31.76 70,31.9 R120.2
  TOP w0.254: U7.AD5 U7.AD4 U7.AD3 ; U7.AD5 U7.AD6 ; U7.AD5 U7.AE5 ; U7.AD6 U7.AE6 ; U7.AD6 U7.AD7 ; U7.G9 U7.G8 ; U7.G8 U7.G7 ; U7.G8 U7.F8 ; U7.G8 U7.H8 U7.H7 ; U7.W17 U7.W16 U7.Y16 ; U7.W17 U7.Y17 ; U7.W17 46.48,15.86 v1(46.51,15.83) 46.52,15.84 U7.V18 U7.U18 47.48,15.42 v1(47.43,15.37) 47.45,15.34 U7.T19 ; U5.14 61.01,33.94 v1(61.76,34.69) ; U7.AE26 U7.AE27 U7.AE28 ; U7.AE26 U7.AE25 ; U7.AE26 42.95,11.84 v1(42.8,11.99) 42.98,12.16 U7.AF25 ; U1.J6 35,51.03 v1(34.9,51.03) 34.9,50.93 U1.H5 ; 15.52,20.57 15.81,20.57 16.18,20.21 C50.1 C49.1 ; J1.2 56.06,68.34 v1(56.13,68.28) ; U7.AE24 U7.AE25 ; U7.AE24 U7.AF24 ; U7.AE24 U7.AE23 ; U7.AE24 U7.AD24 U7.AD25 ; U7.AE25 U7.AF25 ; U7.AE25 U7.AD25 ; U7.AF25 U7.AF24 ; U7.AF25 U7.AG25 U7.AG24 U7.AF24 ; U7.AA15 U7.AA14 U7.AA13 ; U7.AA15 U7.AA16 ; U7.AA15 45.92,17.34 v1(45.94,17.35) 45.98,17.32 U7.Y16 ; U7.AD25 U7.AC25 ; v1(48.48,18.3) 48.52,18.34 v1(49.01,18.34) ; v1(48.48,18.3) U7.R14 ; v1(48.48,18.3) U7.R12 ; U7.AL1 v2(40.06,24.76) ; U2.15 52.59,45.5 52.28,45.19 52.28,45 ; U7.F7 v1(52.98,21.82) 52.96,21.84 U7.G6 ; U7.F7 U7.E7 ; U7.F7 U7.G7 ; U7.F7 U7.F8 ; v1(49.38,15.8) 49.48,15.9 U7.N17 U7.N16 ; v1(49.38,15.8) 49.34,15.84 U7.P18 U7.R18 48.48,15.35 v1(48.45,15.32) ; v1(49.38,15.8) 49.48,15.7 U7.N19 ; U7.AA16 U7.AA17 ; U7.AA16 U7.Y16 ; U7.AA17 U7.AA18 ; U7.AA17 U7.Y17 ; U7.C8 U7.D8 U7.E8 U7.F8 ; U7.Y16 U7.Y17 ; U7.AE5 U7.AE6 ; U7.AE5 43.42,22.34 v1(42.97,21.89) ; U7.AE6 43.03,21.84 42.98,21.89 U7.AF7 ; U7.AE6 U7.AE7 ; U7.R11 U7.P11 U7.P12 ; U7.R11 U7.T11 U7.T12 U7.R12 ; U7.R11 U7.R12 ; v1(48.45,15.32) 48.44,15.34 U7.T19 ; v1(48.45,15.32) 48.48,15.3 U7.R20 ; v1(48.45,15.32) 49,15.32 v1(49.02,15.34) 49.02,15.34 U7.N19 ; U7.T14 U7.R14 ; U7.T14 U7.P14 ; U7.T14 U7.U14 ; U7.T14 U7.T15 U7.T16 ; U7.R14 U7.P14 ; U7.T20 U7.T21 U7.R21 U7.R20 ; U7.T20 U7.R20 ; U7.T20 U7.T19 ; U7.N20 U7.N19 ; U7.AH7 U7.AG7 U7.AF7 ; U7.P12 49.01,18.8 v1(49.01,18.34) ; U7.P12 U7.R12 ; U7.P12 U7.R12 ; U7.P12 49.4,18.84 v1(49.43,18.87) 49.48,18.83 U7.N13 U7.N14 ; 52.28,45 v1(51.53,44.25) ; 52.28,45 U2.14 ; v1(51.53,44.25) 50.78,43.5 U2.8 ; v1(51.53,44.25) 52.28,43.5 U2.9 ; U7.AE7 U7.AD7 ; U7.AE7 U7.AF7 ; U7.AE7 U7.AE8 ; U7.AD7 U7.AC7 ; U4.8 52.31,38.84 v1(51.56,38.09) 51.56,37.97 50.43,36.84 U4.15 ; U7.N16 49.48,17.3 49.45,17.32 v1(49.45,17.35) 49.48,17.37 U7.N14 ; U7.N16 U7.M16 U7.L16 ; U7.AE19 U7.AE20 43.43,14.88 43.02,14.88 U7.AF20 ; U7.G4 U7.G5 U7.G6 ; U7.G7 U7.H7 ; U7.G7 U7.G6 ; C54.2 59.25,25.68 59.17,25.77 R66.1 C46.1 ; U7.P14 48.98,18.31 v1(49.01,18.34) ; U7.P14 U7.N14 ; U5.15 60.04,32.98 60.22,32.8 v1(60.22,32.78) ; U1.A8 29.36,53.37 ; U7.D25 U7.E25 U7.F25 ; U7.H7 U7.J7 v1(51.48,21.82) ; U1.M8 U1.N8 ; U3.11 61.2,43.64 v1(61.95,42.89) ; v1(40.08,9.02) 40.13,9.07 40.21,9.07 U7.AL31 ; C45.2 C44.2 60.49,30.75 60.49,30.75 60.08,30.75 59.96,30.87 59.52,30.87 v1(59.16,30.51) ; v1(33.91,5.99) 33.27,5.35 33.27,3.87 33.73,3.41 C67.2 ; v1(51.01,68.36) 51.02,68.34 J1.3 ; U1.H6 34.32,51 v1(34.32,50.9) ; v1(42.31,2.98) 42.69,3.35 43.81,3.35 R83.2 ; U7.G26 52.52,11.88 52.95,11.88 52.98,11.9 U7.F25 ; U7.G26 U7.G25 ; U7.G26 U7.H26 ; U7.G26 U7.G27 ; U7.G25 U7.G24 ; U7.G25 U7.F25 ; U7.A1 v2(55.77,24.63) ; U6.D1 v1(31.51,23.35)
  TOP w0.305: C39.1 42.1,41.4 42.64,41.94 42.64,42.23 42.99,42.58 R18.2
  TOP w0.381: MOD1.G26 v1(55.9,52.74) ; MOD1.G26 v1(57.3,52.74) ; MOD1.G26 v1(55.9,54.14) ; MOD1.G26 v1(57.3,54.14) ; v1(55.9,52.74) MOD1.G32 v1(55.9,54.14) ; v1(55.9,52.74) MOD1.G25 v1(57.3,52.74) ; v1(55.9,52.74) MOD1.G31 ; C8.2 v1(29.11,57.91) ; U6.P9 v1(23.51,16.15) ; MOD1.G10 v1(60.8,57.64) ; v1(60.8,57.64) MOD1.G11 ; v1(60.8,57.64) MOD1.G16 ; v1(60.8,57.64) MOD1.G17 v1(60.8,59.04) ; MOD1.37 v1(52.21,58.69) ; MOD1.44 v1(51.54,53.79) ; R30.2 45.75,37.77 46,37.52 v1(46,37.46) ; U6.E1 v1(31.51,23.35) ; R56.2 43.12,33.71 43.16,33.75 R49.2 v1(43.87,33.04) ; v1(60.8,54.14) MOD1.G14 v1(60.8,52.74) ; v1(60.8,54.14) MOD1.G15 ; v1(60.8,54.14) MOD1.G9 v1(62.2,54.14) ; v1(60.8,54.14) MOD1.G8 ; R48.2 48.52,32.83 v1(48.49,32.81) ; U8.D8 v1(32.31,6.79) ; v1(62.2,54.14) MOD1.G2 v1(62.2,52.74) ; v1(62.2,54.14) MOD1.G8 ; v1(62.2,54.14) MOD1.G3 ; U6.G1 v1(29.91,23.35) ; MOD1.G8 v1(62.2,52.74) ; MOD1.G8 v1(60.8,52.74) ; v1(62.2,52.74) MOD1.G7 v1(60.8,52.74) ; v1(62.2,52.74) MOD1.G1 ; v1(51.54,60.79) MOD1.34 MOD1.33 ; MOD1.G4 v1(62.2,57.64) ; v1(62.2,57.64) MOD1.G5 v1(62.2,59.04) ; v1(62.2,57.64) MOD1.G11 ; v1(30.64,59.44) C6.2 v1(29.66,58.46) ; MOD1.23 v1(60.45,63.62) ; MOD1.29 v1(56.25,62.78) ; MOD1.G18 v1(60.8,59.04) ; v1(60.8,59.04) MOD1.G11 ; v1(60.8,59.04) MOD1.G12 v1(62.2,59.04) ; C25.2 C28.2 25.54,44.56 25.94,44.96 26.19,44.96 ; Q3.7 Q3.4 29.02,35.59 v1(28.99,35.56) ; U8.J2 v1(27.51,12.39) ; v1(43.82,44.89) C29.2 42.99,44.88 R16.2 R18.2 ; v1(40.54,57.66) 40.6,57.72 C4.2 ; R12.2 v1(24.67,47.56) ; LD1.1 v1(47.04,51.12) ; C53.2 23.33,23.54 v1(23.51,23.35) U6.P1 ; MOD1.61 v1(61.85,48.34) ; U8.G9 v1(29.91,5.99) ; U6.B1 v1(33.91,23.35) ; R34.2 v1(44.15,37.43) ; U8.E2 v1(31.51,12.39) ; v1(26.32,32.89) 26.42,32.99 26.42,33.85 ; C18.2 v1(41.75,51.75) 41.79,51.71 C21.2 ; U8.D1 v1(32.31,13.19) ; v1(60.8,52.74) MOD1.G13 ; U6.B9 v1(33.91,16.15) ; R6.1 v1(32.36,59.51) ; v1(57.3,54.14) MOD1.G20 v1(57.3,52.74) ; v1(57.3,54.14) MOD1.G27 v1(55.9,54.14) ; v1(57.3,54.14) MOD1.G21 ; R64.1 R63.2 59.03,30.25 59.16,30.38 v1(59.16,30.51) ; v1(33.72,41.87) C32.2 34.57,40.97 v1(33.99,40.39) ; v1(65.38,31.44) 65.38,31.44 65.38,31.45 65.8,31.86 R58.2 ; U9.2 67.74,8.22 67.8,8.28 67.8,8.31 v1(67.97,8.48) C57.2 ; U6.A9 v1(34.71,16.15) ; MOD1.9 v1(66.55,55.89) ; U6.D8 v1(32.31,16.95) ; U8.T1 v1(21.91,13.19) 21.12,13.99 R119.1 ; v1(57.3,59.04) MOD1.G30 v1(55.9,59.04) ; v1(57.3,59.04) MOD1.G24 ; v1(57.3,59.04) MOD1.G23 v1(57.3,57.64) ; U6.E2 v1(31.51,22.55) ; U6.M9 v1(25.11,16.15) ; R46.2 v1(42.44,35.76) ; v1(42.31,2.98) 42.31,2.96 42.07,2.71 U11.2 ; MOD1.35 v1(52.21,60.09) ; MOD1.30 v1(55.55,63.54) ; R81.2 v1(41.05,6.24) ; MOD1.31 54.85,62.76 v1(54.9,62.81) ; U8.B9 v1(33.91,5.99) ; v1(40.03,5.08) 40.03,4.95 39.69,4.61 39.69,4.15 ; MOD1.24 v1(59.75,62.78) ; R1.1 24.67,65.81 24.74,65.74 24.74,65.07 v1(24.68,65.02) ; MOD1.G28 v1(55.9,57.64) ; v1(55.9,57.64) MOD1.G34 ; v1(55.9,57.64) MOD1.G29 ; v1(55.9,57.64) MOD1.G35 v1(55.9,59.04) ; MOD1.G29 v1(57.3,57.64) ; MOD1.G29 v1(55.9,59.04) ; v1(57.3,57.64) MOD1.G22 ; U8.B3 v1(33.91,11.59) ; R28.2 v1(38.99,39.45) ; MOD1.7 v1(66.55,54.49) ; U6.J2 v1(27.51,22.55) ; MOD1.16 v1(65.89,60.79) ; v1(55.9,54.14) MOD1.G33 ; v1(57.3,52.74) MOD1.G19 ; v1(55.9,59.04) MOD1.G36 ; v1(26.93,40.03) 25.98,40.03 C33.2 ; MOD1.48 MOD1.49 ; C58.2 v1(65.82,6.45) ; U8.B1 v1(33.91,13.19) ; v1(21.47,30.4) 22.03,30.96 R61.2 ; v1(61.73,22.45) 61.73,21.88 61.43,21.58 D1.5 60.01,21.1 R76.1 ; MOD1.28 v1(56.95,63.54) ; U8.E8 v1(31.51,6.79) ; U6.F9 v1(30.71,16.15) ; U5.8 62.51,35.44 v1(61.76,34.69) 61.01,35.44 U5.9 ; U8.E1 v1(31.51,13.19) ; v1(53.02,33.69) R53.2 51.56,33.69 51.55,33.68 C40.2 ; MOD1.45 v1(52.21,53.09) ; C22.2 v1(43.29,49.33) 43.53,49.33 43.76,49.11 v1(44.22,49.11) ; U8.P9 v1(23.51,5.99) ; C31.2 v1(30.91,42.67) ; v1(62.17,68.26) 62.2,68.29 J2.3 ; U8.M9 v1(25.11,5.99) ; v1(26.83,38.86) 26.49,38.53 25.95,38.53 C38.2 ; 14.85,21.41 C55.2 15.18,22.44 v1(14.76,22.86) ; R31.2 v1(42.63,37.44) ; U6.T9 v1(21.91,16.15) ; MOD1.39 v1(52.21,57.29) ; U8.P1 v1(23.51,13.19) ; U6.J8 v1(28.34,17.78) ; R11.2 v1(48.84,49.09) ; U8.G8 v1(29.91,6.79) ; v1(35.48,41.21) 35.77,40.92 C30.2 ; U6.G8 v1(29.91,16.95) ; U8.G1 v1(29.91,13.19) ; v1(62.2,59.04) MOD1.G6 ; MOD1.1 MOD1.64 63.95,49.25 63.7,49 v1(63.25,49) MOD1.63 ; C27.2 38.65,44.57 37.81,45.41 37.54,45.41 v1(37.1,45.85) ; U6.B3 v1(33.91,21.75) ; 15.78,39.95 15.43,40.3 C34.2 ; v1(48.85,37.44) 48.85,37.47 48.8,37.52 R33.2 ; U8.A9 v1(34.71,5.99) ; U8.J8 v1(27.51,6.79) ; U8.T9 v1(21.91,5.99) ; R51.2 v1(47.04,33.04) ; C26.2 43.72,45.91 v1(43.77,45.95) ; L3.2 21.9,65.77 v1(21.9,64.89) 21.88,64.87 ; U8.F9 v1(30.71,5.99) ; R50.2 45.34,33.67 45.34,33.09 45.32,33.07 v1(45.32,33.04) ; C51.2 25.41,25.4 C52.2 25.39,24.66 25.11,24.39 v1(25.11,23.35) U6.M1 ; U8.M1 v1(25.11,13.19) ; J2.2 v1(67.3,68.29) ; U6.T1 v1(21.91,23.35) ; R32.2 v1(47.32,37.44) ; U6.G9 v1(29.91,16.15) ; U6.E8 v1(31.51,16.95)
  L06_SIG2 w0.102: v1(60.02,25.4) 58.45,23.83 58.45,20.96 57.31,19.81 55.78,19.81 54.51,18.54 52.1,18.54 51.27,17.72 50.74,17.72 50.73,17.72 49.82,17.72 v1(49.45,17.35)
  BOTTOM w0.102: C114.2 49.47,19.45 C113.2 ; C111.1 40.53,19.63 41.15,19.01 42.69,19.01 v1(43.33,18.37) ; C110.1 43.61,20.37 42.97,21 v1(42.97,21.89) ; v1(52.98,11.88) 53.53,12.43 C174.1 ; v1(60.02,25.4) 60.4,25.78 60.4,26.24 60.1,26.54 60.1,27.56 59.72,27.94 58.04,27.94 57.79,27.69 54.71,27.69 54.33,27.31 48.55,27.31 48.4,27.15 46.49,27.15 46.21,26.88 44.1,26.88 43.88,27.1 43.88,27.4 43.9,27.43 43.9,28.39 43.59,28.7 41.31,28.7 39.74,30.28 38.62,30.28 26.02,42.88 24.62,42.88 22.84,44.66 22.84,48.18 23.74,49.07 25.99,49.07 26.39,48.67 27.44,48.67 27.56,48.54 v1(27.99,48.54) ; C136.1 52.16,16.41 52.51,16.06 52.51,15.76 52.48,15.74 52.48,15.73 52.26,15.51 52.25,15.51 52.11,15.37 C148.2 52.05,15.11 52.4,14.76 53.53,14.76 53.61,14.68 C161.1 ; 59.76,24.52 J5.12
  BOTTOM w0.127: C112.1 25.18,17.79 24.71,17.33 24.71,16.55 v1(25.11,16.15)
  BOTTOM w0.14: J3.67 v1(73.32,23.73) ; J5.66 59.48,9.77 59.62,9.63 v1(59.62,9.17) ; J4.65 18.25,34.33 v1(18.9,34.98) ; J4.23 v1(18.02,22.83) ; J3.18 v1(66.83,37.23)
  BOTTOM w0.178: 25.4,31.92 U14.7 ; 25.4,31.92 U14.4 ; 25.4,31.92 U14.21 ; C149.1 37.72,15.22 37.34,15.59 C141.2 37.15,15.9 36.87,16.18 v2(36.72,16.18) ; C87.2 46.75,32.27 47.04,32.57 v1(47.04,33.04) ; C87.2 46.29,30.84 46.2,30.93 C89.2 ; C87.2 47.2,30.84 47.21,30.83 C88.2 ; C117.2 47.18,18.8 46.85,19.13 46.85,19.23 46.68,19.41 C160.1 ; 42.33,2.96 42.43,2.86 42.43,2.83 ; J5.65 64.79,9.77 64.93,9.91 64.93,10.16 v1(64.82,10.27) J5.63 ; J5.12 59.29,24.52 59.04,24.77 v1(58.45,24.77) ; C69.2 v1(49.05,56.91) ; C68.2 v1(49.05,58.4) ; R101.2 53.78,32.93 v1(53.02,33.69) ; v1(32.92,51) 32.92,52.24 32.51,52.65 C70.2
  BOTTOM w0.203: 45.78,14.22 45.78,14.41 46.26,14.89 C153.2 46.26,15.42 46.51,15.67 v1(46.51,15.83) 46.51,16.05 C131.2 ; 45.78,14.22 C168.2 ; 45.78,14.22 45.67,14.33 45.27,14.33 C41.2 ; C152.2 50.42,14.78 C151.2 50.35,14.86 C150.1 49.06,14.86 C159.2 49.03,15.33 v1(49.02,15.34) ; v1(52.67,19.29) 52.69,19.27 52.69,18.96 52.98,18.68 C118.2 ; C138.2 48.11,15.66 48.44,15.32 v1(48.45,15.32) 48.47,15.31 C156.2 C157.2 47.65,14.84 47.55,14.73 47.55,13.97 C171.2 ; C130.2 50.91,16.31 50.53,16.31 C133.1 50.4,16.28 49.64,16.28 C134.1 49.58,16 v1(49.38,15.8) 49.36,15.77 C137.2 ; J4.48 10.53,29.33 v1(10.44,29.24) ; C114.2 49.47,18.91 v1(49.43,18.87) ; v1(49.45,17.35) 49.45,17.62 49.66,17.83 C120.2 C119.2 50.43,17.84 C123.2 ; v1(45.94,17.35) 45.9,17.35 45.55,17.71 C122.2 ; v1(45.94,17.35) 45.6,17.02 C129.2 ; v1(45.94,17.35) 45.94,17.42 46.02,17.5 46.02,17.67 C121.1 ; C117.2 47.91,18.8 C116.2 C115.2 48.54,18.45 48.48,18.39 v1(48.48,18.3) 48.39,18.3 47.98,17.89 C126.2 47.81,17.6 47.74,17.6 47.46,17.32 C124.2 ; v1(14.2,33.25) 13.97,33.48 13.08,33.48 12.93,33.33 J4.62 ; C47.1 18.08,19.79 17.86,19.58 J4.11 ; v1(49.01,18.34) 49.01,18.15 C125.2 ; C172.2 51.8,13.27 C167.1 51.98,13.79 52.05,13.72 52.08,13.72 52.27,13.54 v1(53.6,13.54) 53.61,13.55 C161.1 ; C175.1 50.45,11.48 v1(50.47,11.51) ; U14.10 24.06,33.12 23.78,33.4 ; C139.1 44.45,16.59 C127.2 44.4,16.79 44.07,16.79 43.9,16.97 C128.1 43.44,17.12 43.21,17.35 42.12,17.35 41.83,17.07 C132.1 ; C158.2 47.43,15.22 v1(47.43,15.37) 47.45,15.39 C140.2 ; C180.2 C179.1 ; v1(10.44,27.94) 10.56,27.83 J4.42
  BOTTOM w0.254: J4.45 14.96,28.83 v1(14.14,29.65) ; C182.2 34.77,6.05 v1(34.71,5.99) ; R113.1 55.54,23.12 54.82,22.4 53.56,22.4 v1(52.98,21.82) ; J5.5 62.64,26.27 62.44,26.06 62.44,24.66 62.62,24.48 63.76,24.48 J5.11 ; U13.48 37.45,45.5 v1(37.1,45.85) ; v1(28.99,27.81) 28.99,26.92 28.6,26.54 C48.1 ; C74.2 39.46,49.08 v2(39.27,48.9) ; v1(44.49,57.62) 43.74,56.87 U12.8 ; v1(44.49,57.62) 45.24,58.37 ; v1(44.49,57.62) 43.74,58.37 U12.9 ; J3.77 72.96,20.98 73.08,20.85 73.1,20.85 73.23,20.73 73.92,20.73 74.11,20.54 74.74,20.54 75.11,20.91 v1(75.11,21.41) ; U13.13 58.15,38.96 v1(58.32,38.79) ; v1(25.43,53.79) 26.28,52.94 26.28,52.57 26.79,52.05 C73.2 ; J3.6 v1(66.99,40.73) ; v1(34.71,16.15) 34.79,16.23 C135.2 ; v1(24.46,27.55) 24.46,26.6 C95.1 C96.1 ; v1(10.37,33.12) 10.57,33.33 J4.62 ; v1(40.08,9.02) 40.26,8.83 R122.2 ; U13.36 38.5,38.96 v1(38.99,39.45) ; 45.24,58.37 45.74,58.87 U12.15 ; 45.24,58.37 U12.14 ; U13.25 v1(37.45,32.88) ; J5.17 62.55,22.77 62.23,22.45 v1(61.73,22.45) ; C97.1 20.55,26.98 v1(20.18,27.34) ; J3.24 67.2,35.73 67.19,35.73 67.16,35.73 66.96,35.92 66.96,35.96 66.86,36.07 v1(66.86,36.17) ; J3.12 v1(66.83,38.98) ; C180.2 v1(45.88,7.97) ; v1(30.26,28.45) 30.64,28.83 30.64,30.97 30.45,31.16 R102.1 R99.2 ; v1(13.39,23.62) 13.19,23.83 J4.28 ; v1(28.34,17.78) 28.34,17.27 28.46,17.15 C145.2 ; C91.2 51.28,31.95 v1(53.02,33.69) ; v1(27.51,6.79) 27.55,6.83 R132.1 ; C78.2 34.1,48.43 34.57,48.9 35.23,48.9 C76.2 35.27,49.34 v1(35.62,49.7) ; J3.11 v1(73.51,38.98)
  BOTTOM w0.305: v2(55.99,9.75) 55.99,9.26 55.83,9.1 55.06,9.1 C176.2 55.01,9.09 54.27,9.09 C177.2 53.5,9.09 C178.2 ; C103.2 C102.2 C101.2 C100.2 48.26,24.96 48.41,25.1 C99.1 ; R113.1 R112.1
  BOTTOM w0.381: 61.83,18.52 61.83,19.94 61.6,20.17 v1(61.6,20.27) ; 61.83,18.52 J5.34 ; 61.83,18.52 J5.33 ; v1(23.51,16.15) 23.51,15.76 23.67,15.6 C146.2 ; C163.2 32.27,13.96 31.86,13.55 31.86,13.53 31.52,13.19 v1(31.51,13.19) ; v1(14.89,17.4) 14.89,17.97 15.03,18.11 15.03,19.36 15.25,19.58 J4.11 ; C90.2 23.18,28.67 23.61,28.24 C94.2 ; C147.2 21.76,16 v1(21.91,16.15) ; v1(27.51,6.79) 28.33,5.97 C185.2 ; v1(23.51,13.19) 23.85,13.53 C166.2 ; 34.85,39.15 33.79,39.15 33.48,39.46 33.48,39.89 v1(33.08,40.3) ; 34.85,39.15 C80.2 v1(33.99,40.39) ; 34.85,39.15 C81.2 C82.2 ; v1(21.91,23.35) 21.72,23.55 C108.1 C109.1 ; v1(21.47,30.4) 21.96,30.89 C86.1 ; C186.2 25.45,5.66 v1(25.11,5.99) ; C181.2 67.96,8.47 v1(67.97,8.48) ; C79.2 44.07,46.25 v1(43.77,45.95) 43.51,46.2 R97.1 ; v1(9.91,19.25) 10.23,19.58 J4.12 ; C94.2 25.56,28.24 C92.2 26.6,28.29 C93.2 v1(26.62,27.61) ; C94.2 v1(24.46,27.55) ; v1(23.51,5.99) 23.54,5.96 C187.2 ; J3.56 J3.55 73.5,26.98 73.69,27.17 74.2,27.17 74.57,26.8 74.57,26.76 v1(74.73,26.59) ; v1(25.11,13.19) 25.79,13.87 C165.2 ; 53.61,14.2 54.11,14.71 C155.2 ; J3.34 J3.33 v1(73.52,32.98) ; J4.55 15.2,31.58 14.74,31.12 14.74,31.01 14.48,30.76 v1(14.2,30.76) ; C188.2 21.64,5.71 v1(21.91,5.99) ; J4.77 v1(19.99,37.58) ; C142.2 25.57,15.59 25.31,15.85 25.31,15.95 v1(25.11,16.15) ; v1(33.91,16.15) 34.17,15.89 C143.2 ; v1(31.51,23.35) 31.56,23.39 31.56,23.61 31.57,23.62 31.57,23.68 31.86,23.97 C104.2 ; R92.2 v1(45.19,52.61) ; J5.56 v1(58.23,12.52) ; J4.78 v1(10.08,37.58) ; J4.34 9.94,25.58 v1(9.29,26.23) ; C106.2 29.98,23.42 v1(29.91,23.35) ; v1(13.47,31.47) 13.36,31.58 J4.56 10.52,31.58 10.11,31.17 v1(10.06,31.17) ; J3.77 J3.78 ; C184.2 30.24,5.67 v1(29.91,5.99) ; J5.55 64.67,12.52 64.7,12.55 v1(64.89,12.55) ; C107.2 35.23,24 C105.2 34.05,23.48 v1(33.91,23.35) ; C170.2 35.44,13.97 C162.2 34.17,13.45 v1(33.91,13.19) ; v2(36.72,16.18) 37.61,17.07 C132.1 ; v1(42.31,2.98) 42.33,2.96 42.33,2.93 42.43,2.83 C189.2 ; v1(33.91,5.99) 33.91,5.21 C183.2 ; C72.2 31.05,51 31.69,51 31.77,51.08 v1(32.34,51.08) ; J4.33 14.97,25.58 v1(14.76,25.78) ; C173.2 28.33,12.68 27.97,12.32 27.59,12.32 v1(27.51,12.39) ; v1(19.44,12.81) C169.1 C154.1 ; C144.2 30.36,15.69 30.14,15.92 30.14,15.92 v1(29.91,16.15) ; v1(29.91,13.19) 30.36,13.64 C164.2 ; v1(51.48,21.82) 51.41,21.75 50.82,21.75 50.47,22.1 50.47,24.54 49.91,25.1 C99.1 ; J5.11 v1(65.79,24.52)
  BOTTOM w0.508: v1(61.76,34.69) 62.97,35.9 C83.2
  vias: v1(7.9,29.59) v1(8.16,68.58) v1(8.16,67.69) v1(8.16,66.42) v1(8.09,65.26) v1(8.09,63.99) v1(8.28,62.74) v1(8.28,61.85) v1(9.15,29.31) v1(9.44,62.8) v1(9.44,61.91) v1(9.55,6.73) v1(10.09,35.21) v1(10.44,11.56) v1(10.71,62.8) v1(10.71,61.91) v1(10.7,14.73) v1(11.73,62.8) v1(12.48,9.78) v1(13,62.8) v1(13.87,57.13) v1(13.87,56.41) v1(13.87,55.35) v1(13.87,54.64) v1(13.87,53.57) v1(13.87,52.86) v1(13.87,51.79) v1(13.87,51.08) v1(14.13,24.77) v1(14.13,24.13) v1(14.13,23.5) v1(14.13,22.86) v1(14.13,2.67) v1(14.27,62.8) v1(14.27,61.91) v1(14.48,57.92) v1(14.48,50.45) v1(14.51,11.68) v1(14.76,24.77) v1(14.76,24.13) v1(14.76,23.5) v1(15.54,62.8) v1(15.54,61.91) v1(15.52,43.18) v1(15.52,42.55) v1(15.52,41.91) v1(16.16,43.18) v1(16.16,42.55) v1(16.16,41.91) v1(16.81,62.8) v1(16.81,61.91) v1(18.08,62.8) v1(18.08,61.91) v1(19.35,62.8) v1(19.35,61.91) v1(20.22,33.61) v1(20.44,65.35) v1(20.45,64.52) v1(20.64,63.56) v1(20.62,62.8) v1(20.62,61.91) v1(20.6,36.33) v1(21.14,65.81) v1(21.3,69.13) v1(21.3,67.74) v1(21.89,63.81) v1(21.89,62.8) v1(21.89,61.91) v1(22.36,69.04) v1(22.31,67.69) v1(22.66,66.02) v1(22.92,63.83) v1(22.92,62.82) v1(22.92,61.93) v1(23.27,58.5) v1(23.43,69.08) v1(23.43,67.68) v1(23.63,65.99) v1(24.03,47.63) v1(24.19,63.83) v1(24.19,62.82) v1(24.19,61.93) v1(24.29,58.5) v1(24.77,69.11) v1(24.77,67.71) v1(25.18,58.5) v1(25.2,32.28) v1(25.3,32.89) v1(25.46,63.83) v1(25.46,62.82) v1(25.46,61.93) v1(25.81,65.79) v1(25.84,32.31) v1(26.04,69.11) v1(26.04,67.71) v1(26.04,58.29) v1(26.04,57.4) v1(26.04,56.52) v1(26.04,55.63) v1(26.04,54.86) v1(26.19,65.02) v1(26.45,32.26) v1(26.73,63.83) v1(26.73,62.82) v1(26.73,61.93) v1(26.7,45.97) v1(26.83,65.66) v1(26.83,45.21) v1(27.31,69.11) v1(27.31,67.71) v1(27.72,65.15) v1(27.72,64.26) v1(28,62.82) v1(28,61.93) v1(28.58,69.11) v1(28.58,67.71) v1(28.6,66.68) v1(28.6,64.39) v1(28.6,63.5) v1(28.99,28.45) v1(29.27,62.82) v1(29.27,61.93) v1(29.49,65.79) v1(29.49,63.5) v1(29.62,28.45) v1(29.62,27.81) v1(29.85,69.11) v1(29.85,67.71) v1(29.87,66.8) v1(30.26,42.67) v1(30.26,42.04) v1(30.26,41.4) v1(30.26,27.81) v1(30.46,48.34) v1(30.51,65.79) v1(30.51,64.9) v1(30.54,62.82) v1(30.54,61.93) v1(30.89,42.04) v1(30.89,41.4) v1(31.12,69.11) v1(31.12,67.71) v1(31.4,65.15) v1(31.65,64.39) v1(31.65,62.74) v1(31.6,61.9) v1(32.18,66.1) v1(32.39,69.11) v1(32.39,67.71) v1(32.62,62.69) v1(32.59,61.88) v1(32.71,64.46) v1(33.45,66.1) v1(33.66,69.11) v1(33.66,67.71) v1(33.89,62.69) v1(33.91,61.9) v1(33.98,64.46) v1(34.72,66.1) v1(34.93,69.11) v1(34.93,67.71) v1(35.16,62.69) v1(35.25,64.46) v1(35.18,61.9) v1(35.99,66.1) v1(36.1,54.86) v1(36.1,54.1) v1(36.2,69.11) v1(36.2,67.71) v1(36.43,62.69) v1(36.45,61.9) v1(36.52,64.46) v1(37.26,66.1) v1(37.47,69.11) v1(37.47,67.71) v1(37.7,62.69) v1(37.72,61.9) v1(37.79,64.46) v1(38.31,53.02) v1(38.53,66.1) v1(38.74,69.11) v1(38.74,67.71) v1(39.06,64.46) v1(38.97,62.69) v1(38.99,61.9) v1(39.8,66.1) v1(40.01,69.11) v1(40.01,67.71) v1(40.24,62.69) v1(40.26,61.9) v1(40.33,64.46) v1(40.54,56.39) v1(41.07,66.1) v1(41.18,57.66) v1(41.18,56.39) v1(41.28,69.11) v1(41.28,67.71) v1(41.51,62.69) v1(41.53,61.9) v1(41.6,64.46) v1(41.81,57.66) v1(41.81,56.39) v1(42.55,69.11) v1(42.55,67.71) v1(42.75,62.71) v1(42.75,61.93) v1(42.95,66.07) v1(43.45,64.5) v1(43.47,57.62) v1(43.82,69.11) v1(43.82,67.71) v1(44.02,62.71) v1(44.02,61.93) v1(44.22,66.07) v1(44.29,28.12) v1(44.72,64.5) v1(44.68,27.74) v1(45.09,69.11) v1(45.09,67.71) v1(45.29,62.71) v1(45.29,61.93) v1(45.49,66.07) v1(45.5,57.62) v1(45.99,64.5) v1(46.36,69.11) v1(46.36,67.71) v1(46.33,27.59) v1(46.56,62.71) v1(46.56,61.93) v1(46.76,66.07) v1(47.26,64.5) v1(47.35,28.09) v1(47.63,69.11) v1(47.63,67.71) v1(47.83,62.71) v1(47.83,61.93) v1(48.03,66.07) v1(48.53,64.5) v1(48.49,28.96) v1(48.57,32.19) v1(48.85,62.71) v1(48.85,61.93) v1(48.9,69.11) v1(48.9,67.71) v1(49.3,66.07) v1(49.66,28.88) v1(49.8,64.5) v1(50.12,62.71) v1(50.12,61.93) v1(50.17,69.11) v1(50.17,67.71) v1(50.57,66.07) v1(51.07,64.5) v1(51.18,69.11) v1(51.39,62.71) v1(51.39,61.93) v1(51.53,45.27) v1(51.53,43.24) v1(51.56,39.11) v1(51.56,37.08) v1(51.64,66.78) v1(51.79,2.62) v1(52.38,62.69) v1(52.56,66.57) v1(52.81,65.58) v1(52.81,64.47) v1(53.32,62.69) v1(54.13,59.69) v1(54.13,58.42) v1(54.13,57.15) v1(54.13,55.88) v1(54.13,54.61) v1(54.13,53.34) v1(54.13,52.07) v1(54.13,50.8) v1(54.13,2.59) v1(54.41,65.05) v1(54.44,64.14) v1(54.55,65.84) v1(54.68,66.75) v1(54.87,63.5) v1(55.15,60.91) v1(55.15,55.88) v1(55.36,64.69) v1(55.4,50.8) v1(56.11,69.11) v1(56.25,65.58) v1(56.42,60.91) v1(56.42,55.88) v1(56.52,67.71) v1(56.52,66.44) v1(56.63,64.69) v1(56.67,50.8) v1(57.52,65.58) v1(57.69,60.91) v1(57.69,55.88) v1(57.79,68.98) v1(57.79,67.71) v1(57.79,66.44) v1(57.9,64.69) v1(57.94,50.8) v1(58.79,65.58) v1(58.96,60.91) v1(59.06,68.98) v1(59.06,67.71) v1(59.06,66.44) v1(59.08,59.06) v1(59.08,57.66) v1(59.08,56.26) v1(59.08,54.86) v1(59.08,53.47) v1(59.08,52.07) v1(59.08,50.8) v1(59.17,64.69) v1(60.06,65.58) v1(60.23,60.91) v1(60.33,68.98) v1(60.33,67.71) v1(60.33,66.44) v1(60.44,64.69) v1(60.48,50.8) v1(61.33,65.58) v1(61.5,60.91) v1(61.6,67.71) v1(61.6,66.44) v1(61.71,64.69) v1(61.75,50.8) v1(61.76,35.71) v1(61.76,33.68) v1(61.95,44.16) v1(61.95,41.62) v1(62.6,65.58) v1(62.77,60.91) v1(62.87,66.44) v1(62.98,64.69) v1(63.33,63.45) v1(63.81,66.75) v1(63.87,65.58) v1(63.99,64.29) v1(64.04,60.91) v1(64.04,59.44) v1(64.06,55.96) v1(64.57,28.35) v1(64.7,40.41) v1(64.77,62.66) v1(65.36,26.75) v1(65.54,28.35) v1(65.54,22.51) v1(65.79,66.73) v1(65.77,65.33) v1(65.82,62.69) v1(65.89,27) v1(66.04,66.19) v1(66.16,64.44) v1(66.2,62.23) v1(66.93,62.77) v1(67.04,65.33) v1(67.31,67.46) v1(67.31,66.19) v1(67.43,64.44) v1(67.92,63.02) v1(68.16,61.56) v1(68.16,60.29) v1(68.21,68.68) v1(68.31,65.33) v1(68.58,67.46) v1(68.58,66.19) v1(68.86,63.5) v1(69.24,37.36) v1(69.25,35.92) v1(69.48,68.68) v1(69.52,63.19) v1(69.52,61.92) v1(69.52,60.65) v1(69.52,59.38) v1(69.52,58.11) v1(69.52,56.84) v1(69.52,55.57) v1(69.52,54.3) v1(69.52,53.03) v1(69.52,51.76) v1(69.52,50.49) v1(69.52,49.22) v1(69.52,47.95) v1(69.52,46.68) v1(69.52,38.63) v1(69.6,67.71) v1(69.6,66.44) v1(69.75,1.91) v1(69.97,64.44) v1(70.53,63.32) v1(70.53,62.05) v1(70.53,60.78) v1(70.53,59.51) v1(70.53,58.24) v1(70.53,56.97) v1(70.53,55.7) v1(70.53,54.43) v1(70.53,53.16) v1(70.53,51.89) v1(70.53,50.62) v1(70.53,49.35) v1(70.53,48.08) v1(70.53,46.81) v1(70.57,35.33) v1(70.74,68.47) v1(70.74,67.2) v1(70.85,65.33) v1(70.84,25.93) v1(71,24.08) v1(71.24,64.44) v1(71.17,39.6) v1(71.28,37.69) v1(71.66,65.91) v1(71.76,68.85) v1(71.76,67.58) v1(71.73,64.06) v1(71.73,62.79) v1(71.73,61.52) v1(71.73,60.25) v1(71.73,58.98) v1(71.73,57.71) v1(71.73,56.44) v1(71.73,55.17) v1(71.87,53.79) v1(71.87,52.52) v1(71.87,51.25) v1(71.87,49.98) v1(71.87,48.71) v1(71.87,47.44) v1(71.87,46.55) v1(72.12,65.33) v1(72.6,66.17) v1(72.62,64.06) v1(72.62,62.79) v1(72.62,61.52) v1(72.62,60.25) v1(72.62,58.98) v1(72.62,57.71) v1(72.62,56.44) v1(72.62,55.17) v1(72.8,65.51) v1(73.04,69.06) v1(73.14,53.79) v1(73.14,52.52) v1(73.14,51.25) v1(73.14,49.98) v1(73.14,48.71) v1(73.14,47.44) v1(73.14,46.55) v1(73.46,24.87) v1(73.56,66.18) v1(73.8,68.04) v1(74.31,69.06) v1(74.38,66.12) v1(74.41,53.79) v1(74.41,52.52) v1(74.41,51.25) v1(74.41,49.98) v1(74.41,48.71) v1(74.41,47.44) v1(74.41,46.55) v1(74.45,6.6) v1(74.69,68.04) v1(74.68,26.04) v1(75.2,69.06) v1(75.19,66.14) v1(75.47,4.95) v1(75.68,53.79) v1(75.68,52.52) v1(75.68,51.25) v1(75.68,49.98) v1(75.68,48.71) v1(75.68,47.44) v1(75.68,46.55) v1(75.98,1.65) v1(76.47,69.06) v1(76.86,68.33) v1(76.95,53.79) v1(76.95,52.52) v1(76.95,51.25) v1(76.95,49.98) v1(76.95,48.71) v1(76.95,47.44) v1(76.95,46.55) v1(76.99,67.56) v1(77.37,3.3) v1(77.74,69.06) v1(77.74,67.79) v1(77.75,66.8) v1(78.26,68.45) v1(78.22,53.79) v1(78.22,52.52) v1(78.22,51.25) v1(78.22,49.98) v1(78.22,48.71) v1(78.22,47.44) v1(78.22,46.55) v1(78.26,44.58) v1(78.26,43.05) v1(78.26,41.66) v1(78.39,67.31)
